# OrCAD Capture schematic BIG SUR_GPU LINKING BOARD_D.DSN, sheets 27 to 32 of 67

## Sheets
27 P27  PCIe Clock Generator-1: size C
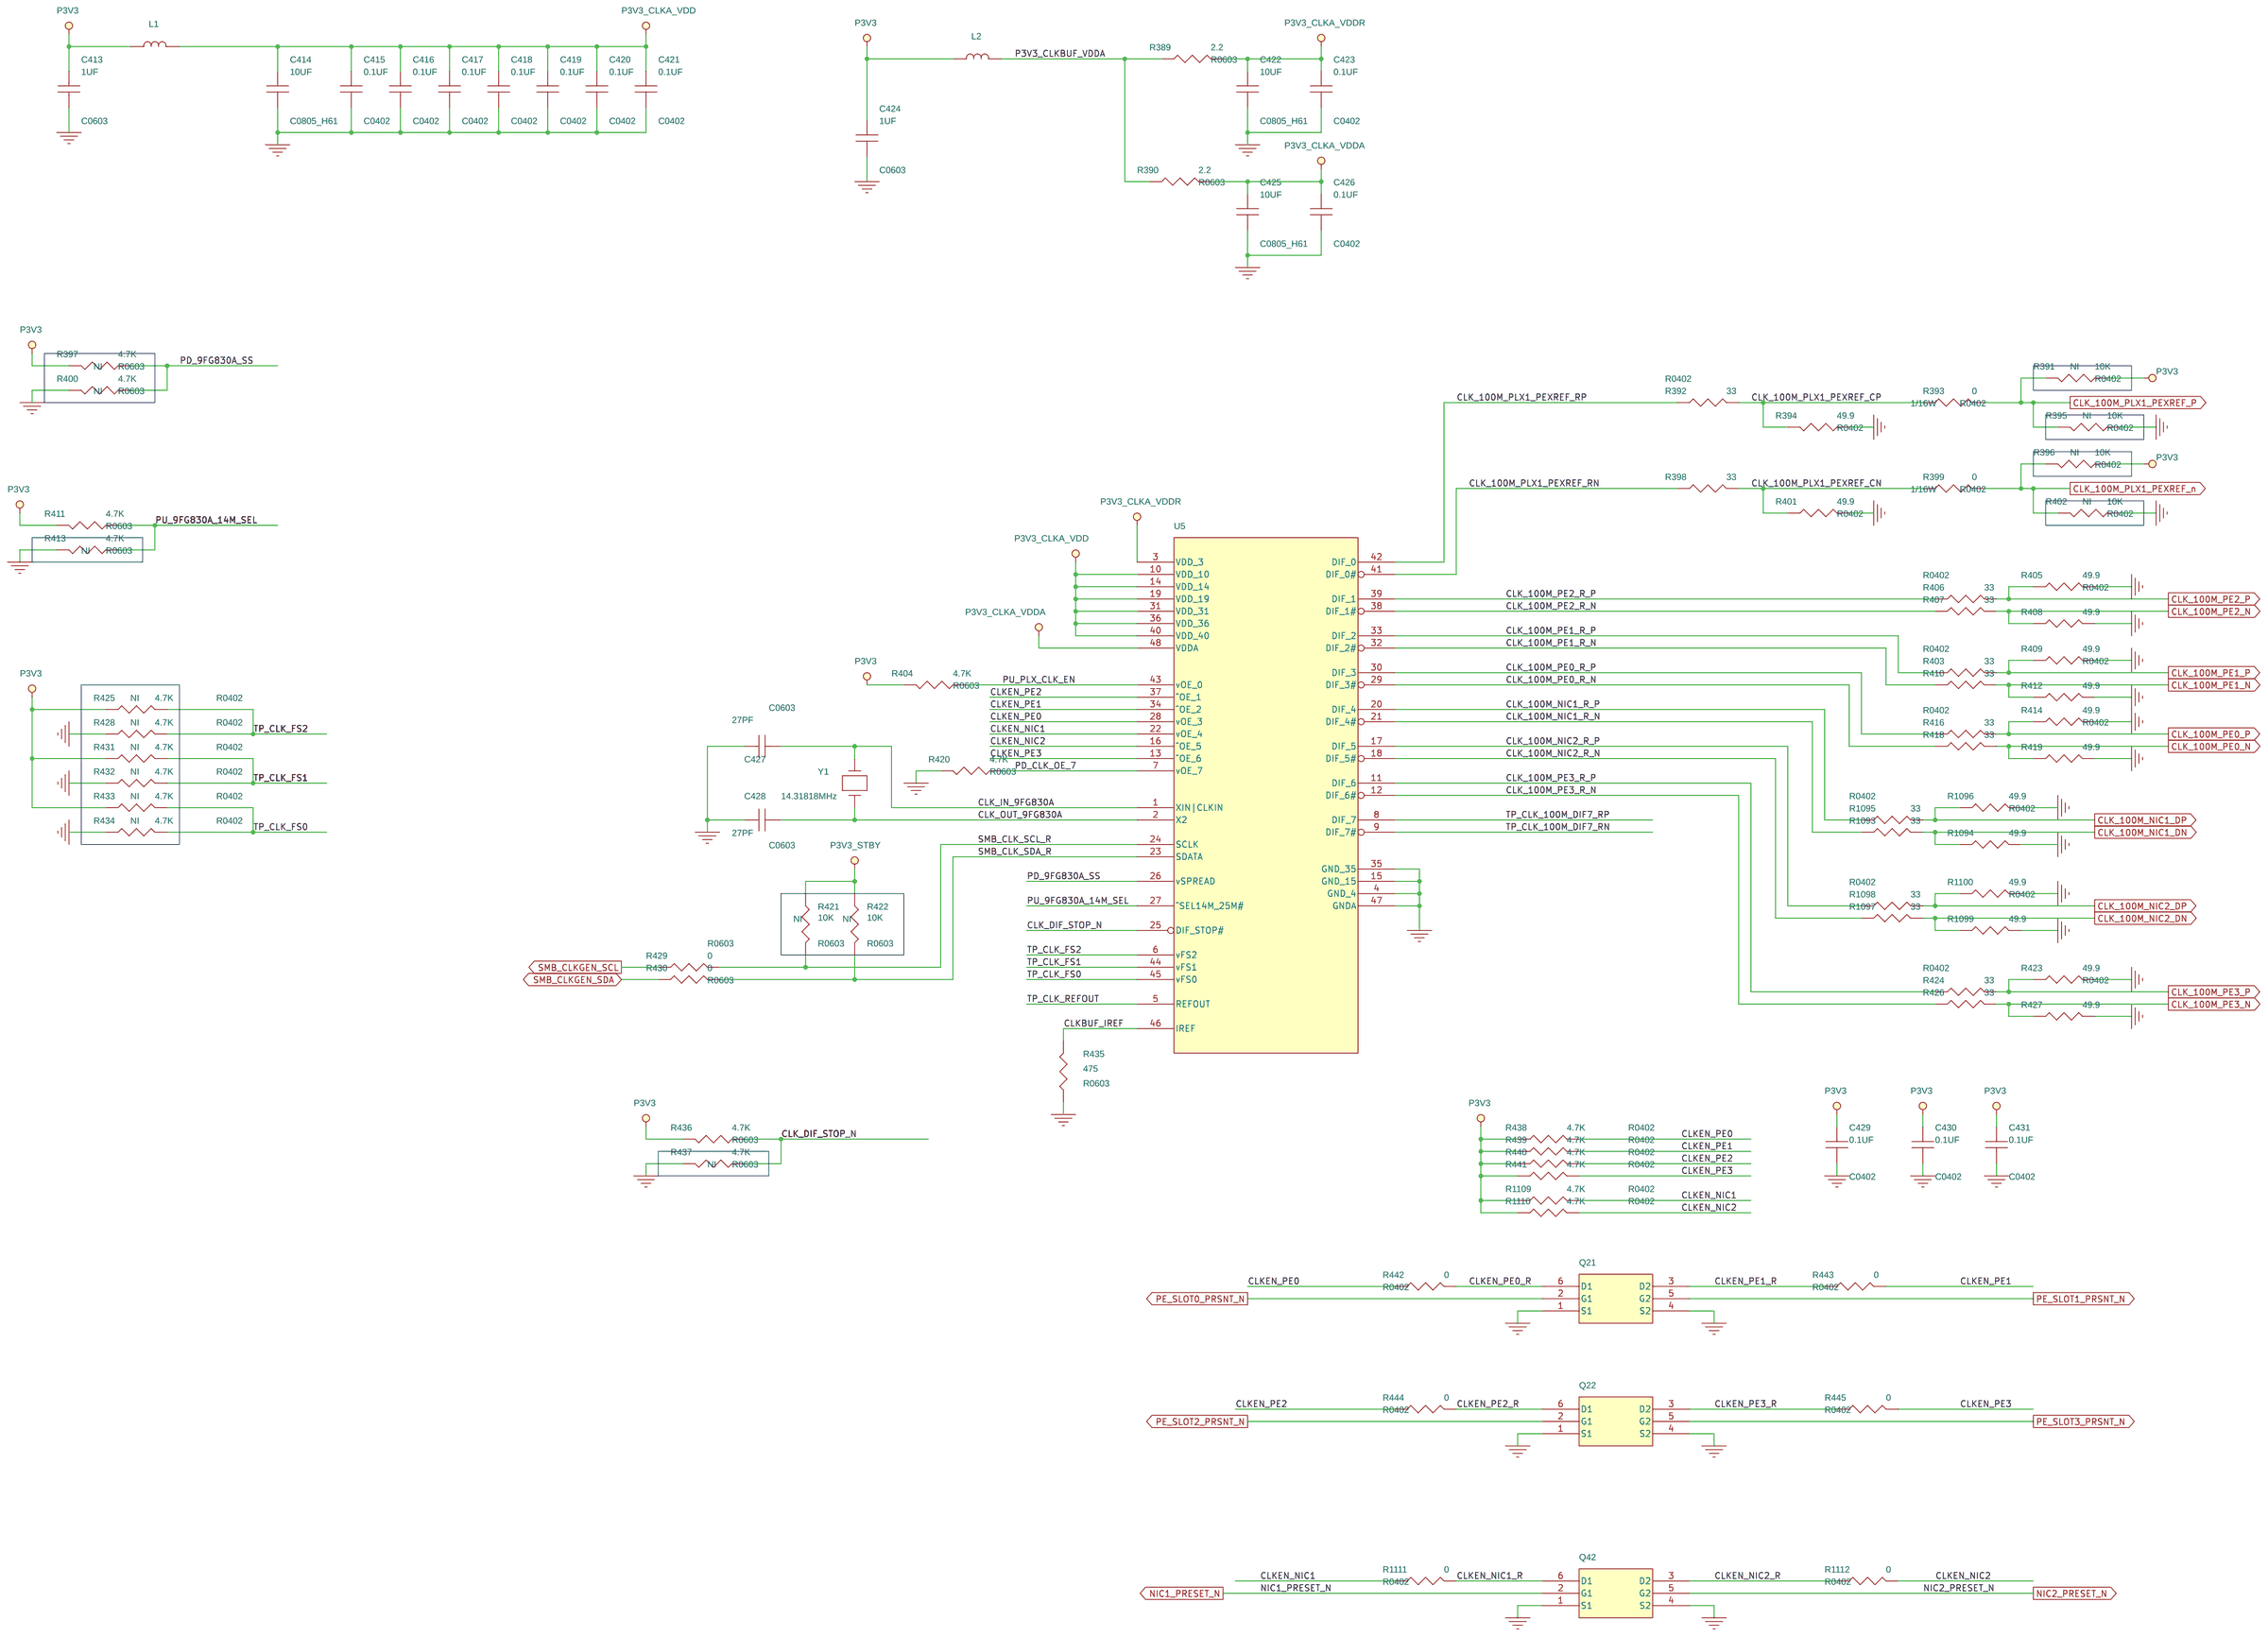
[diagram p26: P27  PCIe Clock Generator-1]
28 P28  PCIe Clock Generator-2: size C
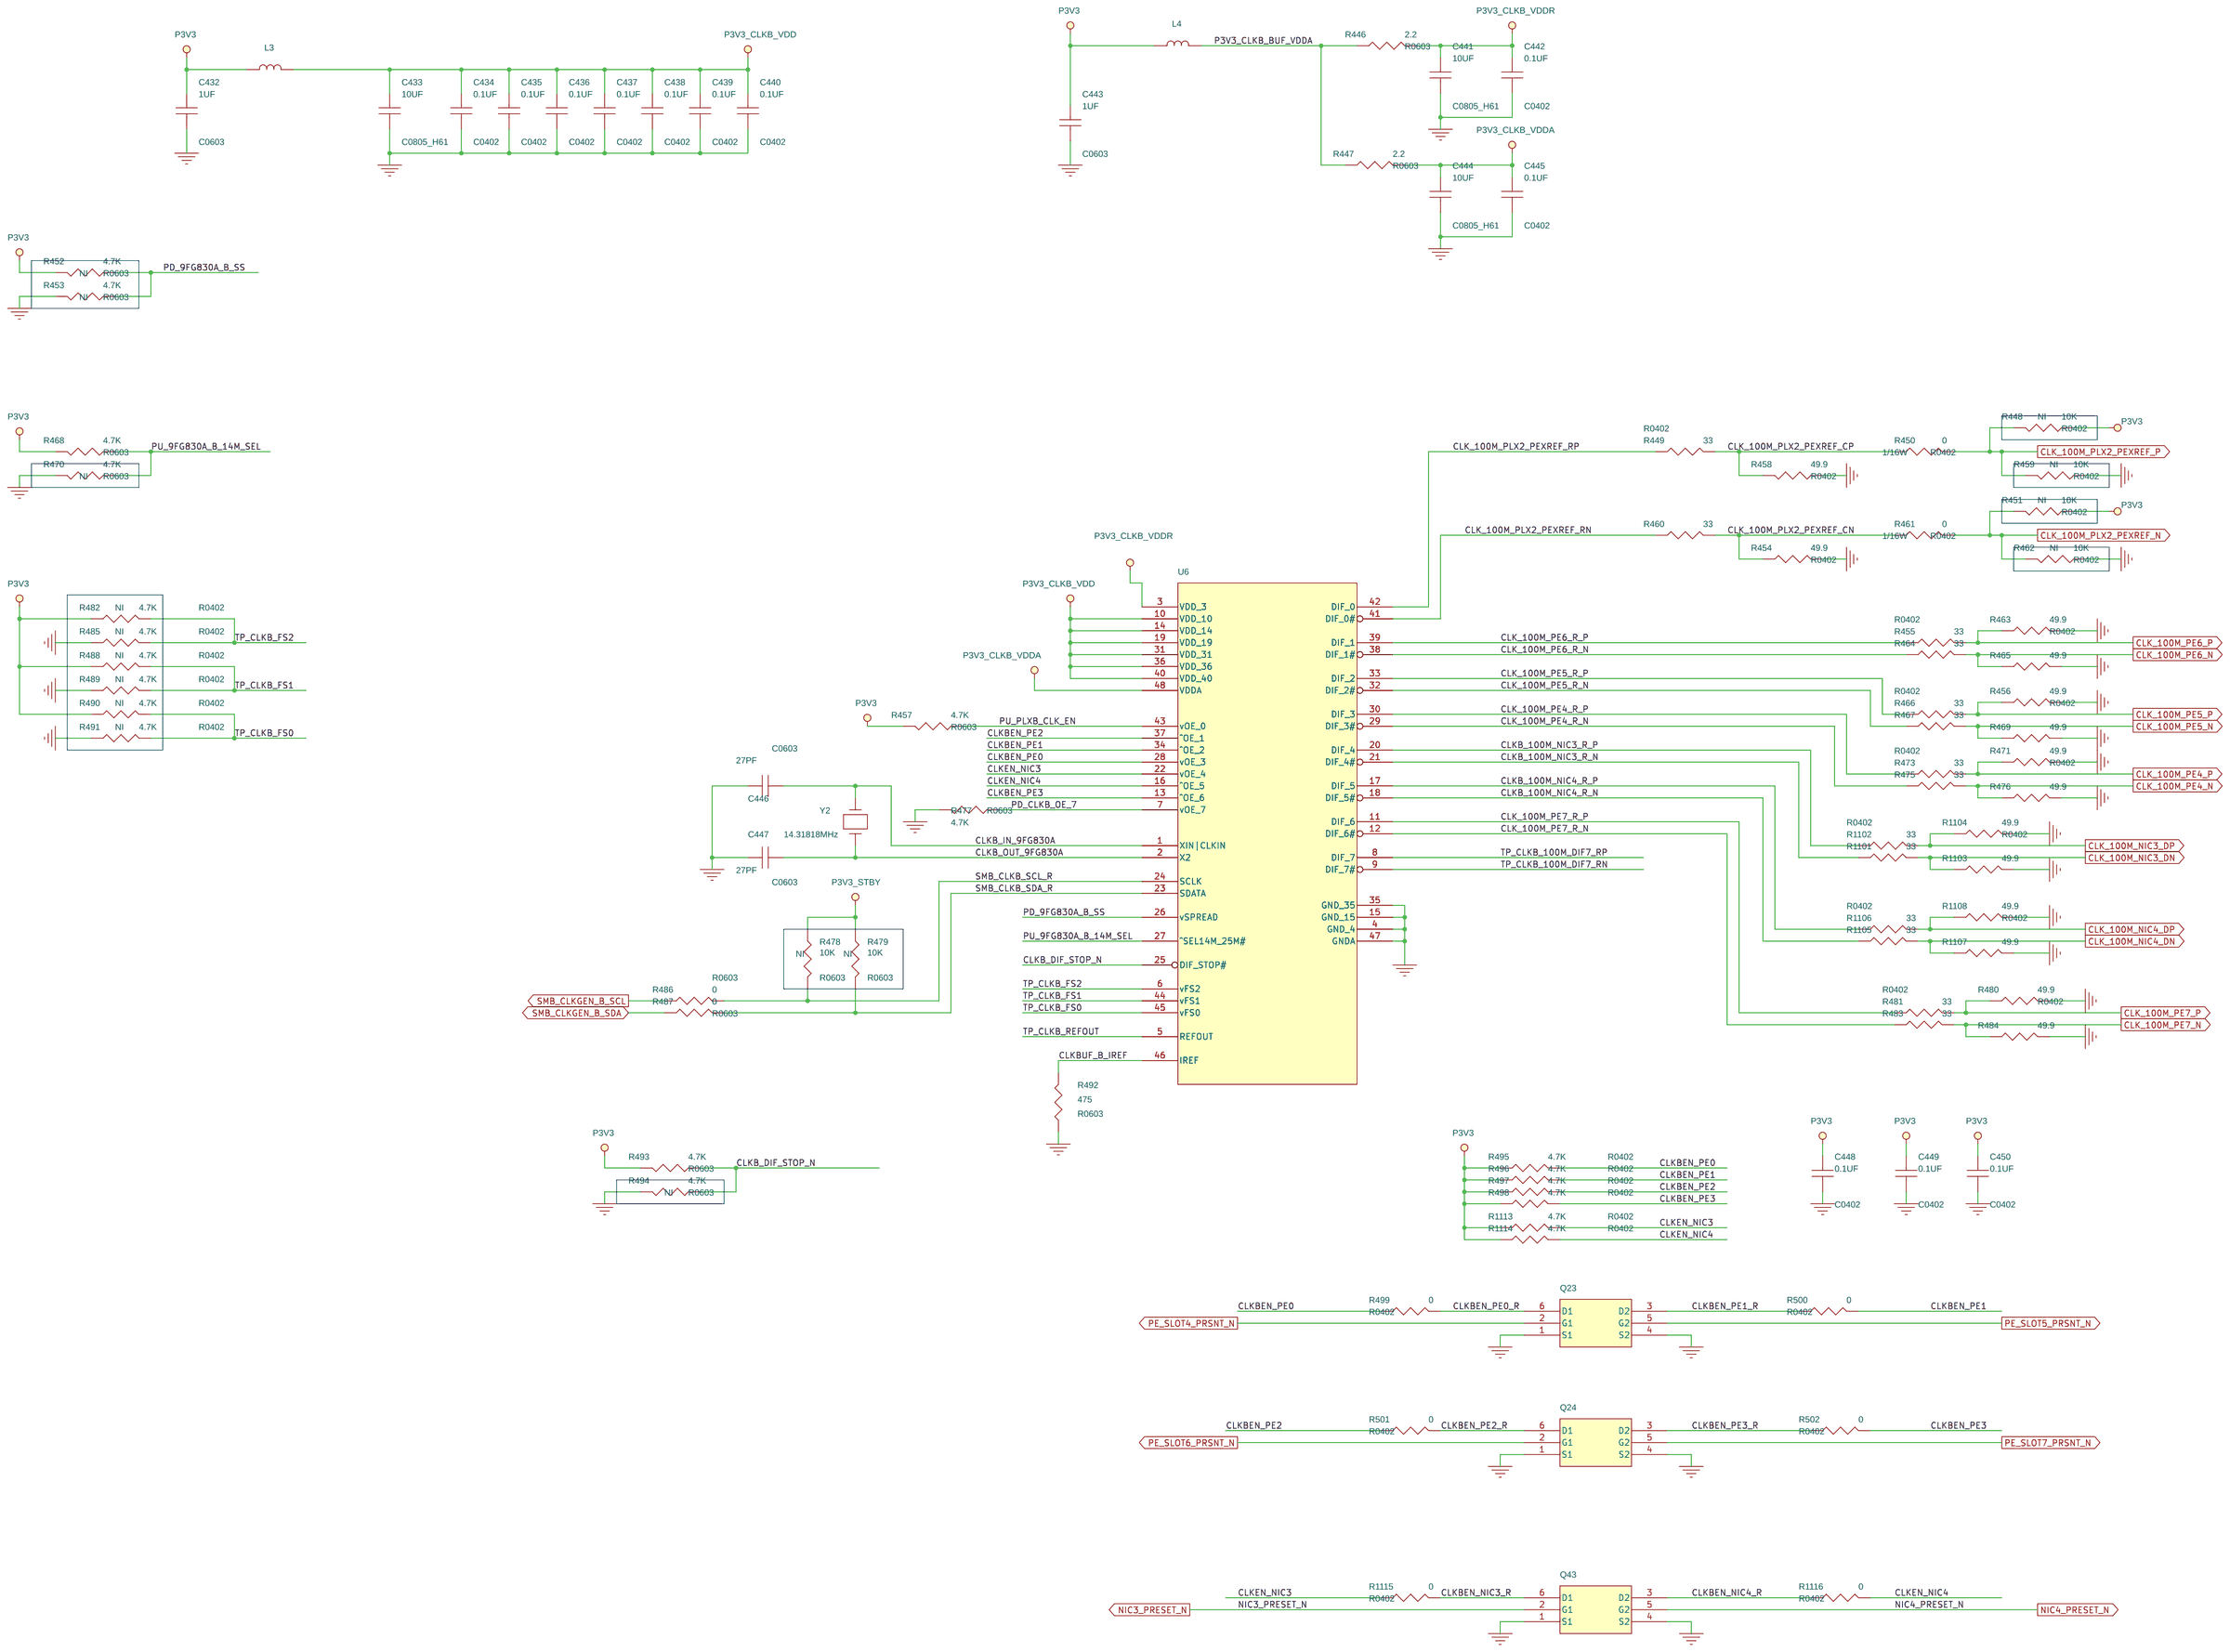
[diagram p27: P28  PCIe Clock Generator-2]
29 P29  MINI SAS HD Conn- A&B: size C
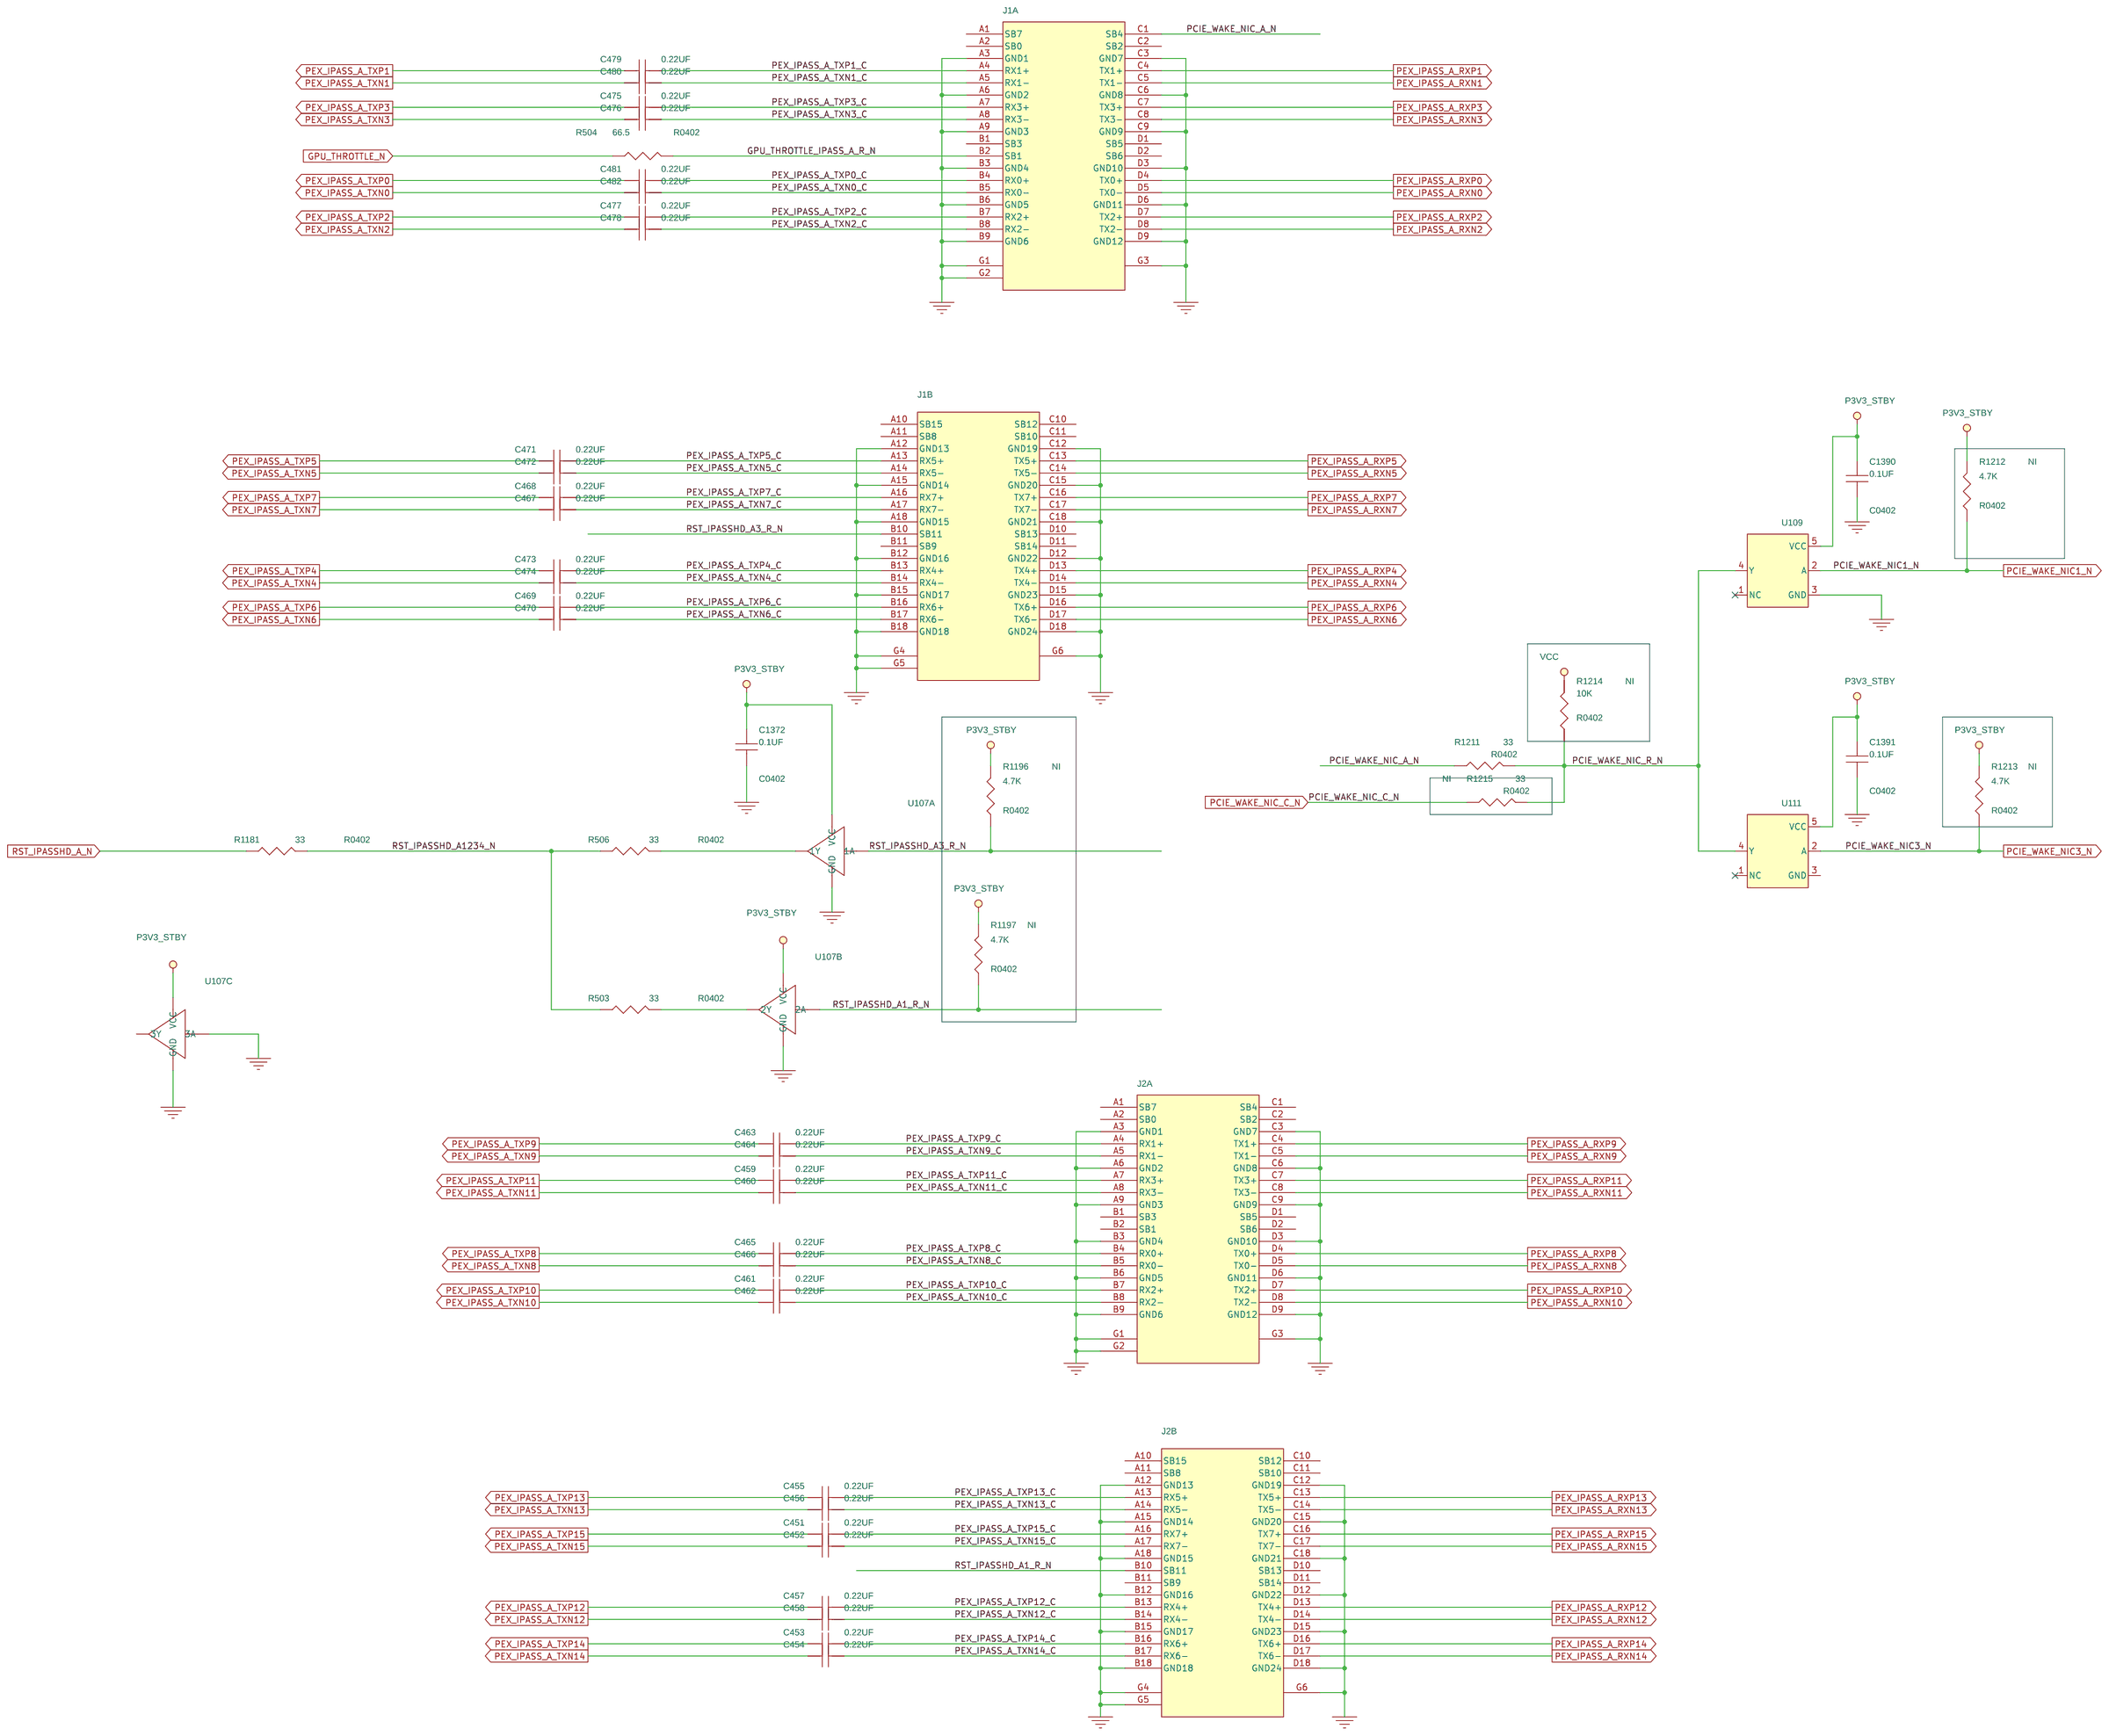
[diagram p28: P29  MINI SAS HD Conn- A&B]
30 P30  MINI SAS HD Conn-C&D: size C
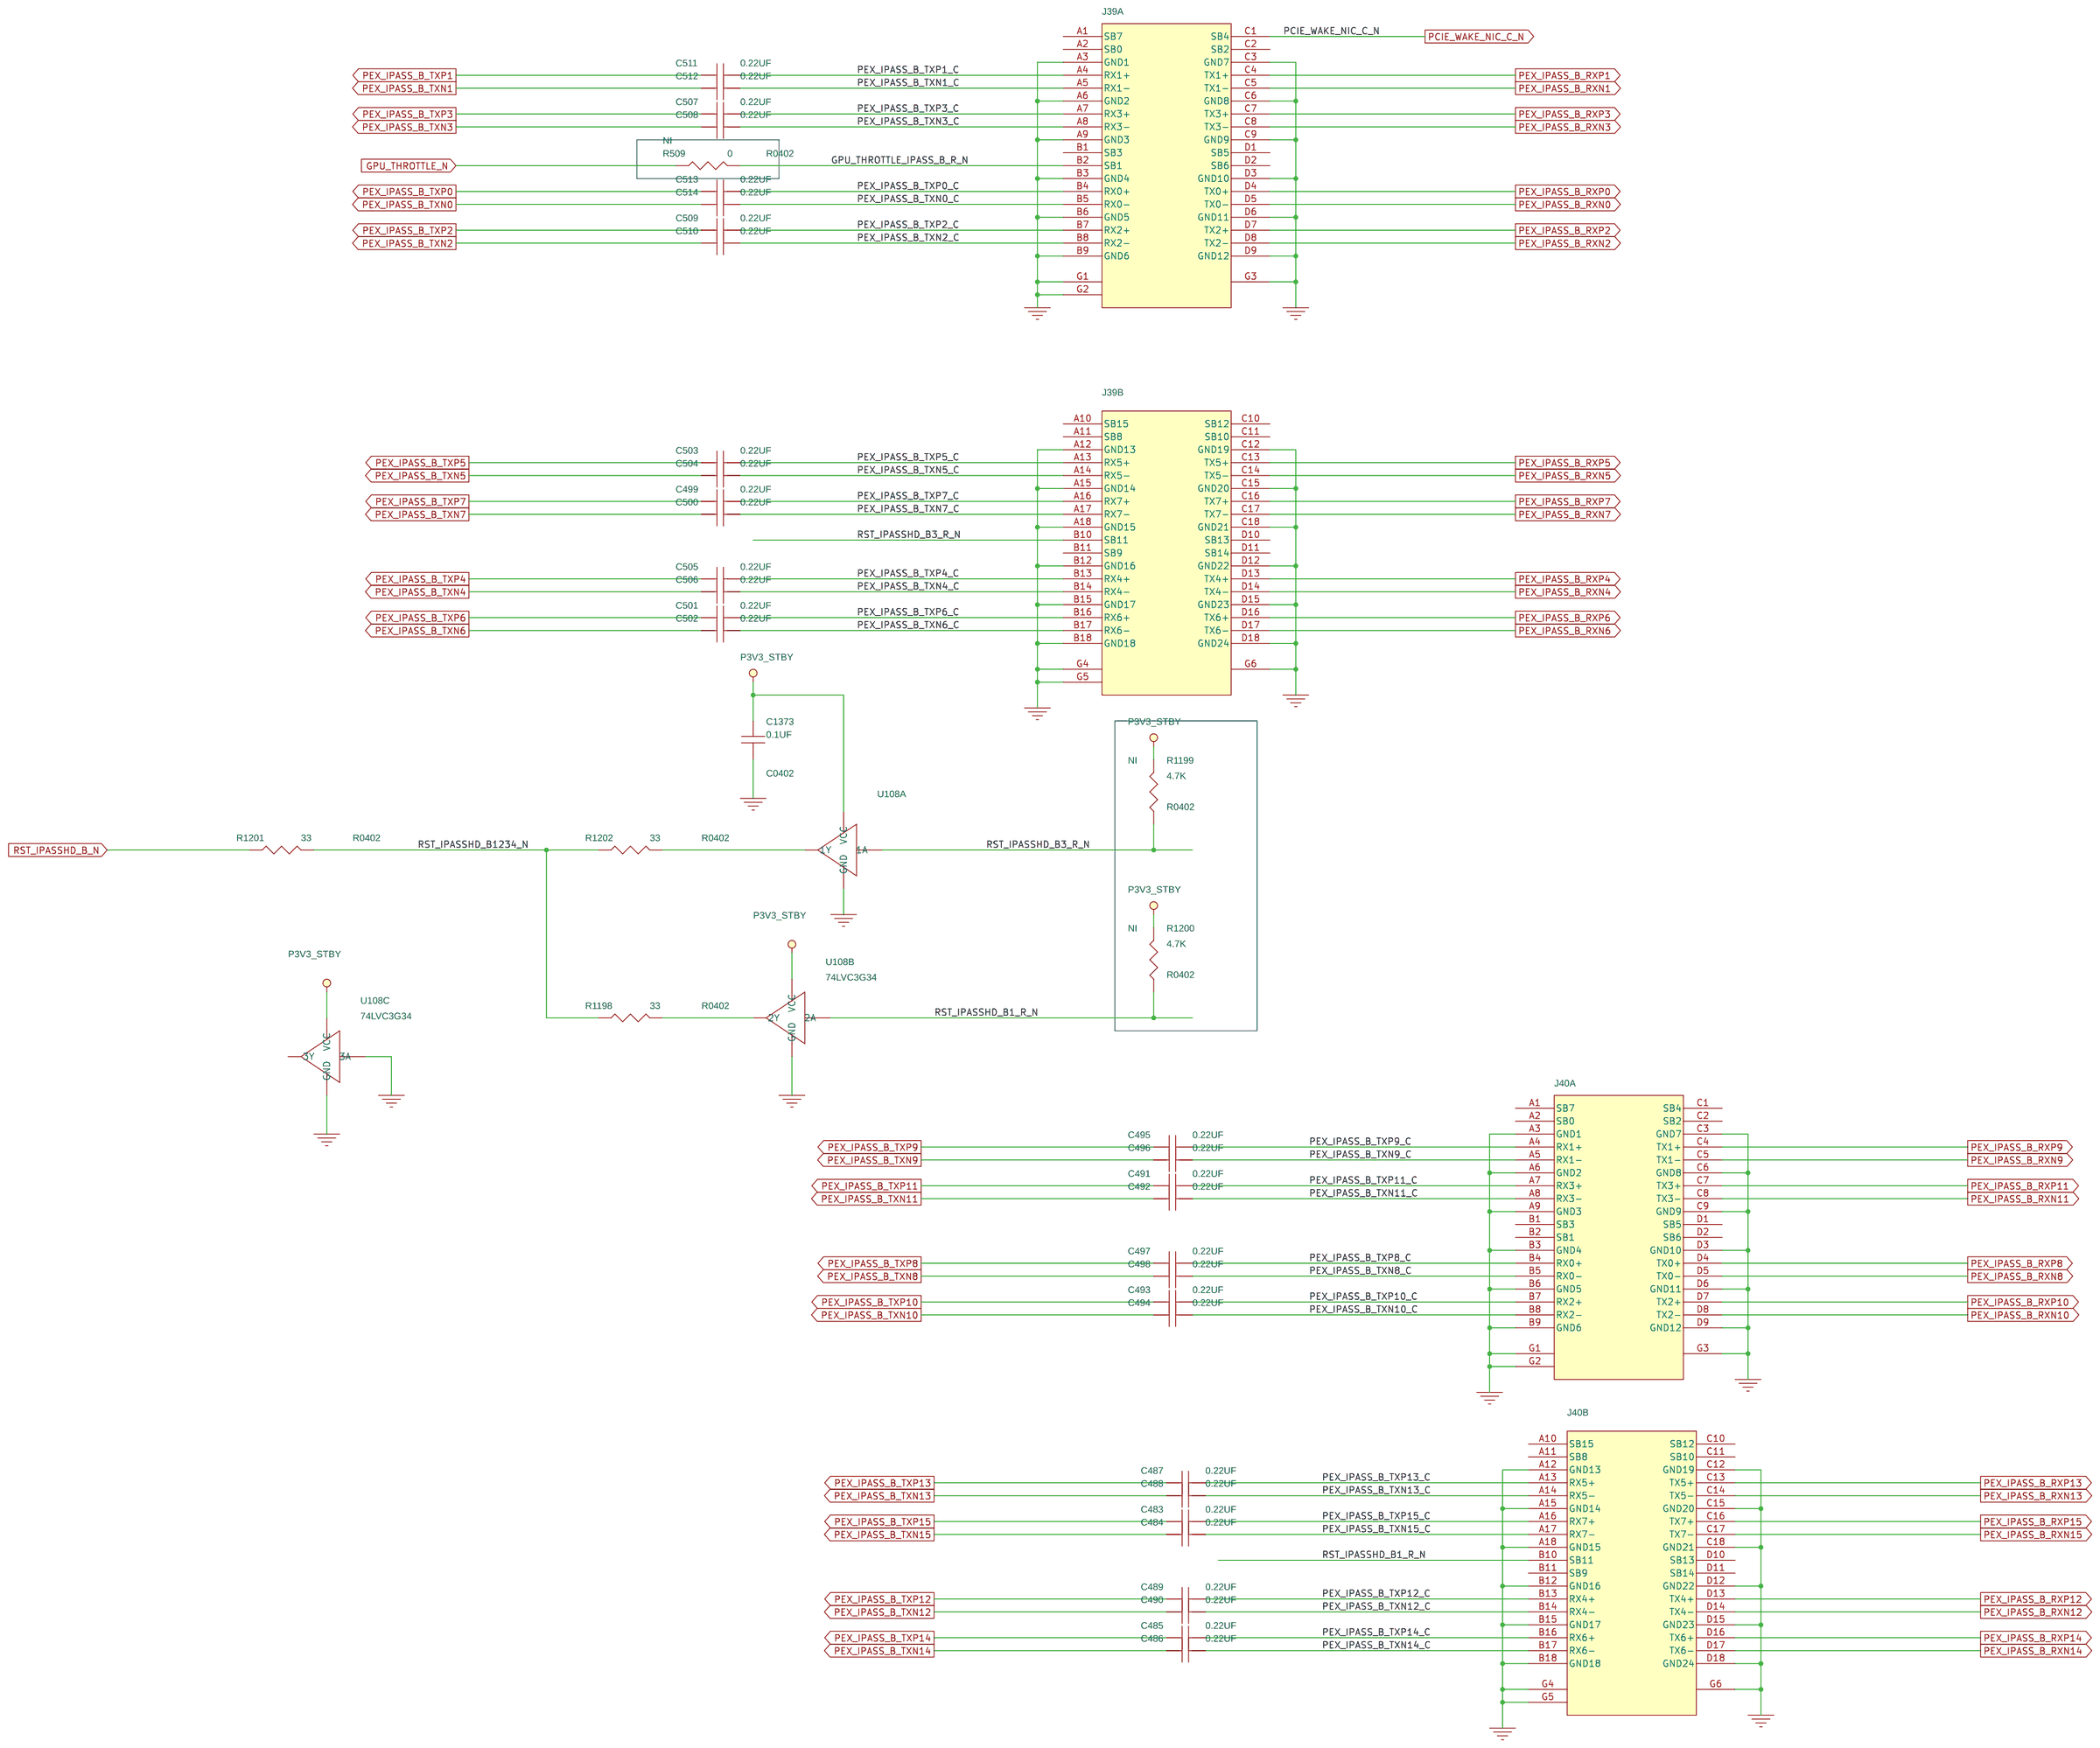
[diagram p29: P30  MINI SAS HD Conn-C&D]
31 P31  PCIe x16 Slot-0: size C
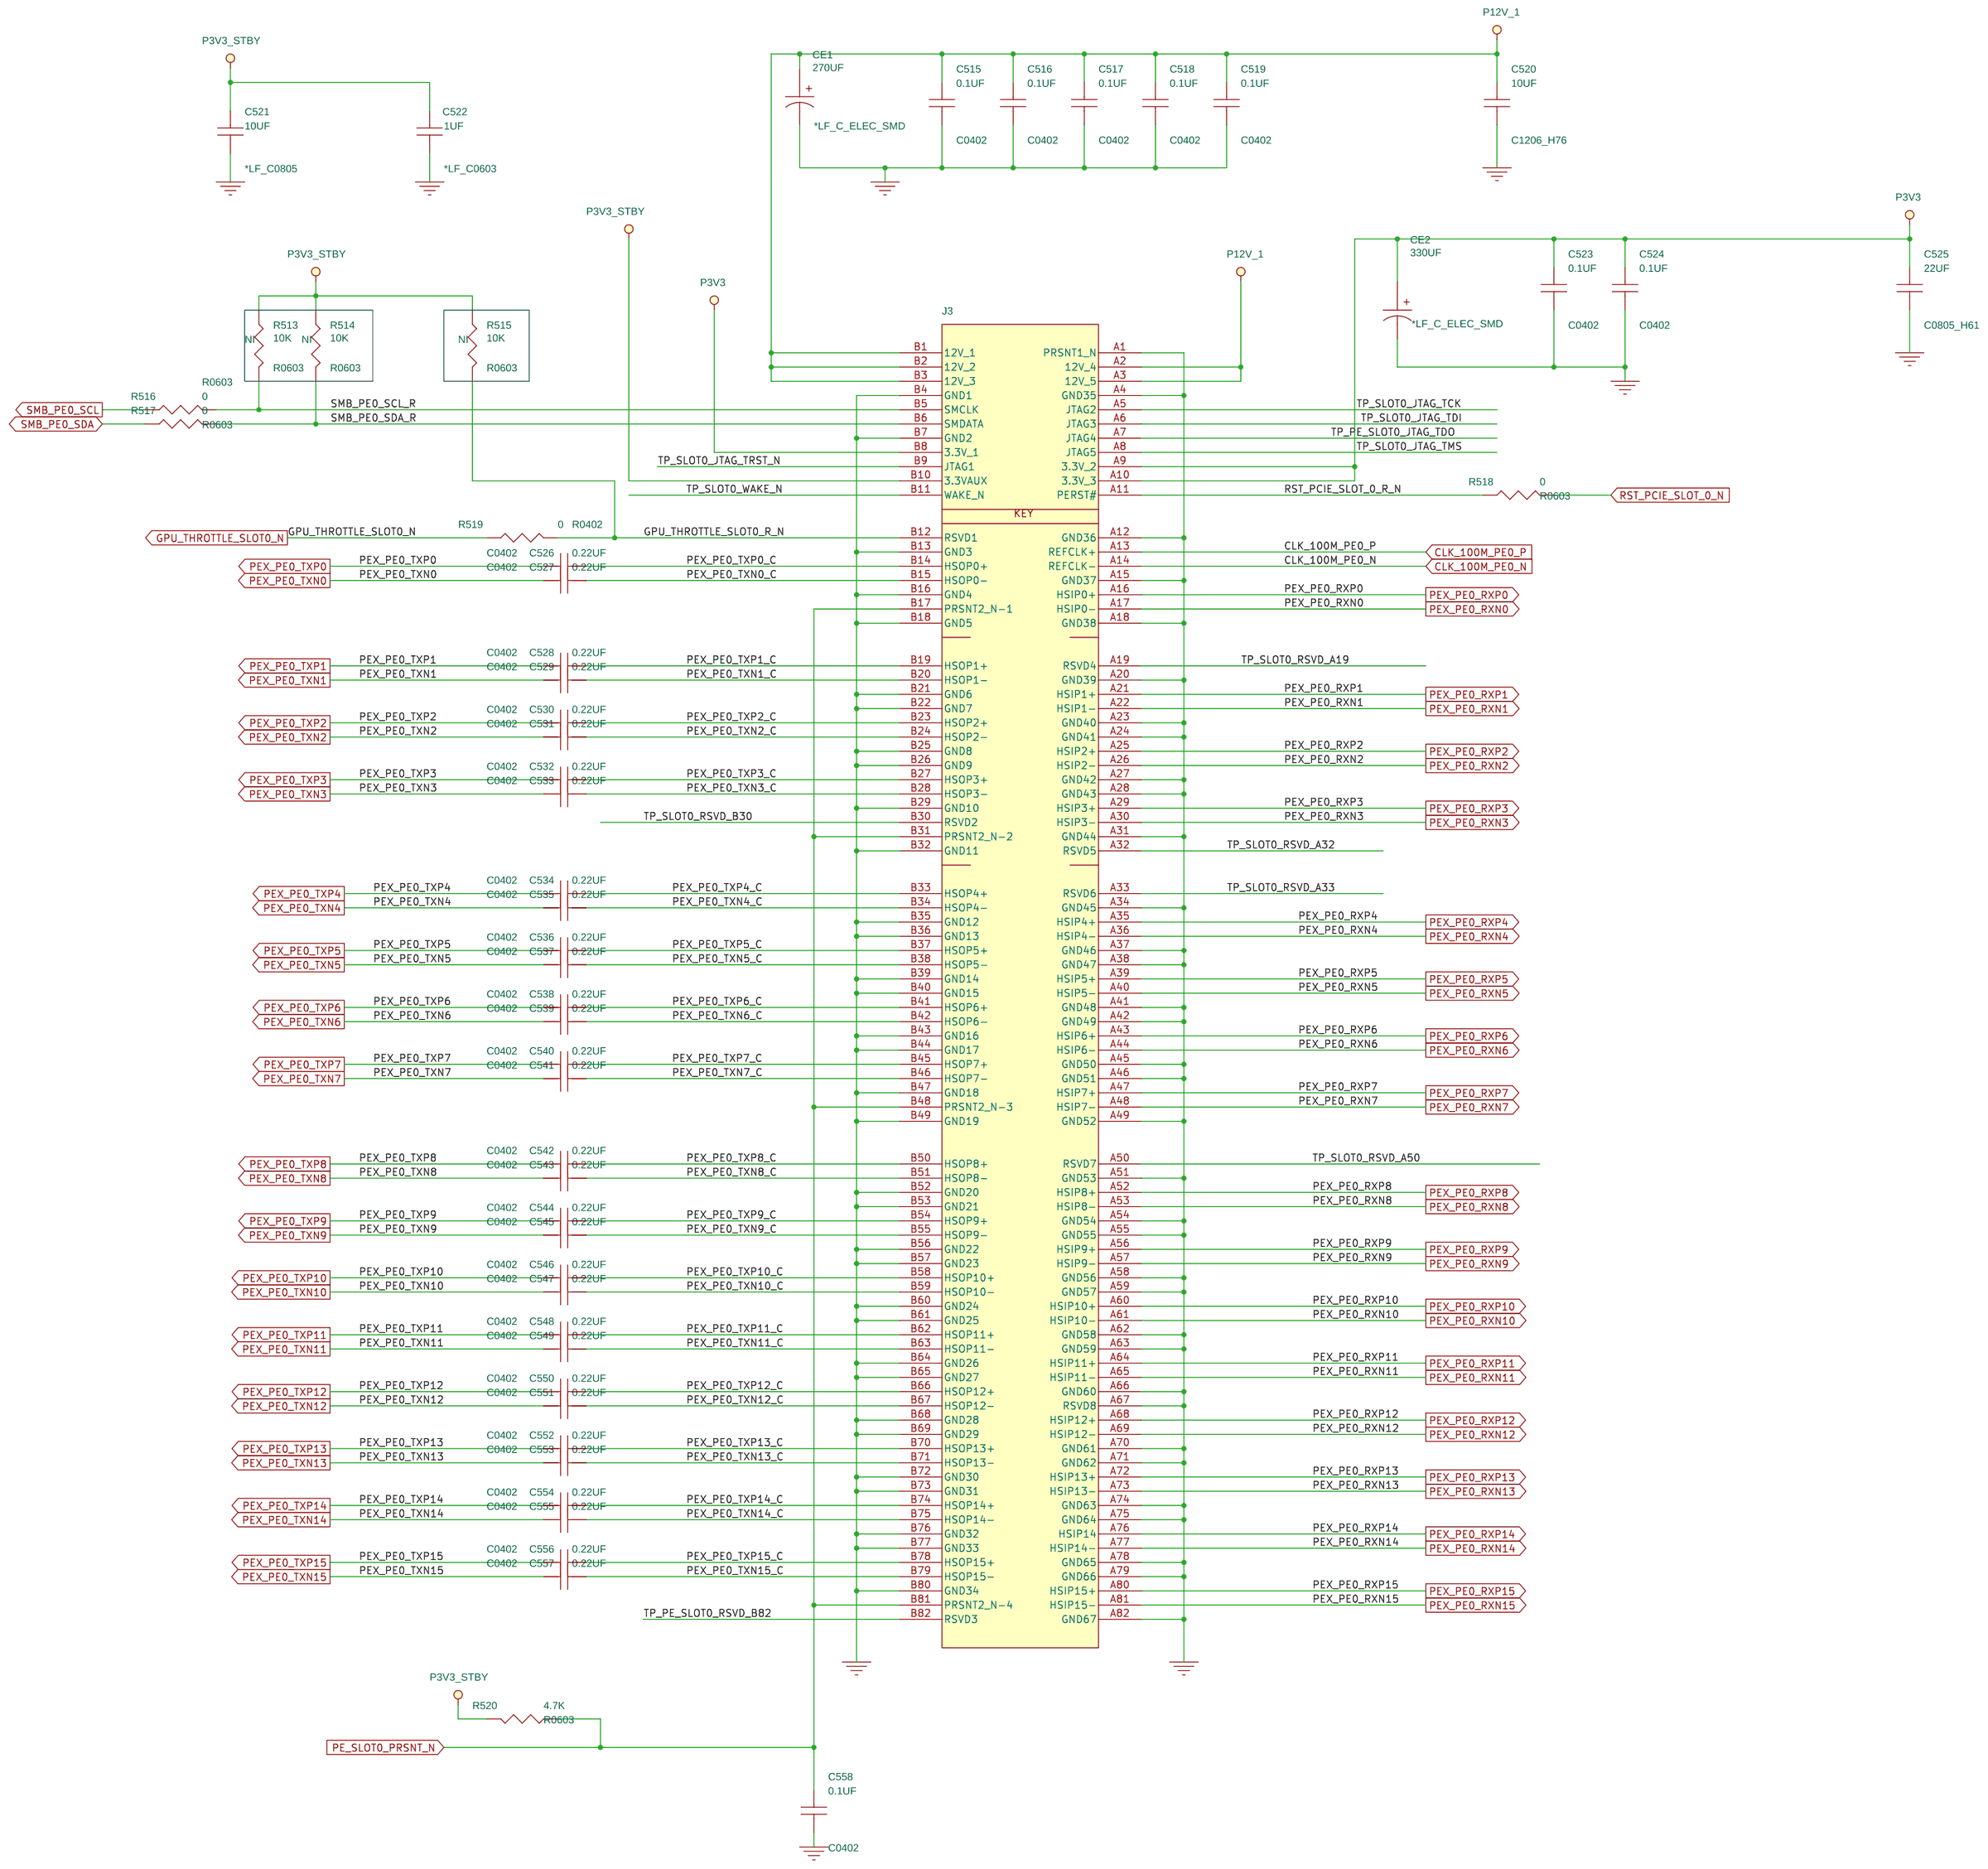
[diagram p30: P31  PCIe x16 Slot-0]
32 P32  PCIe x16 Slot-1: size C
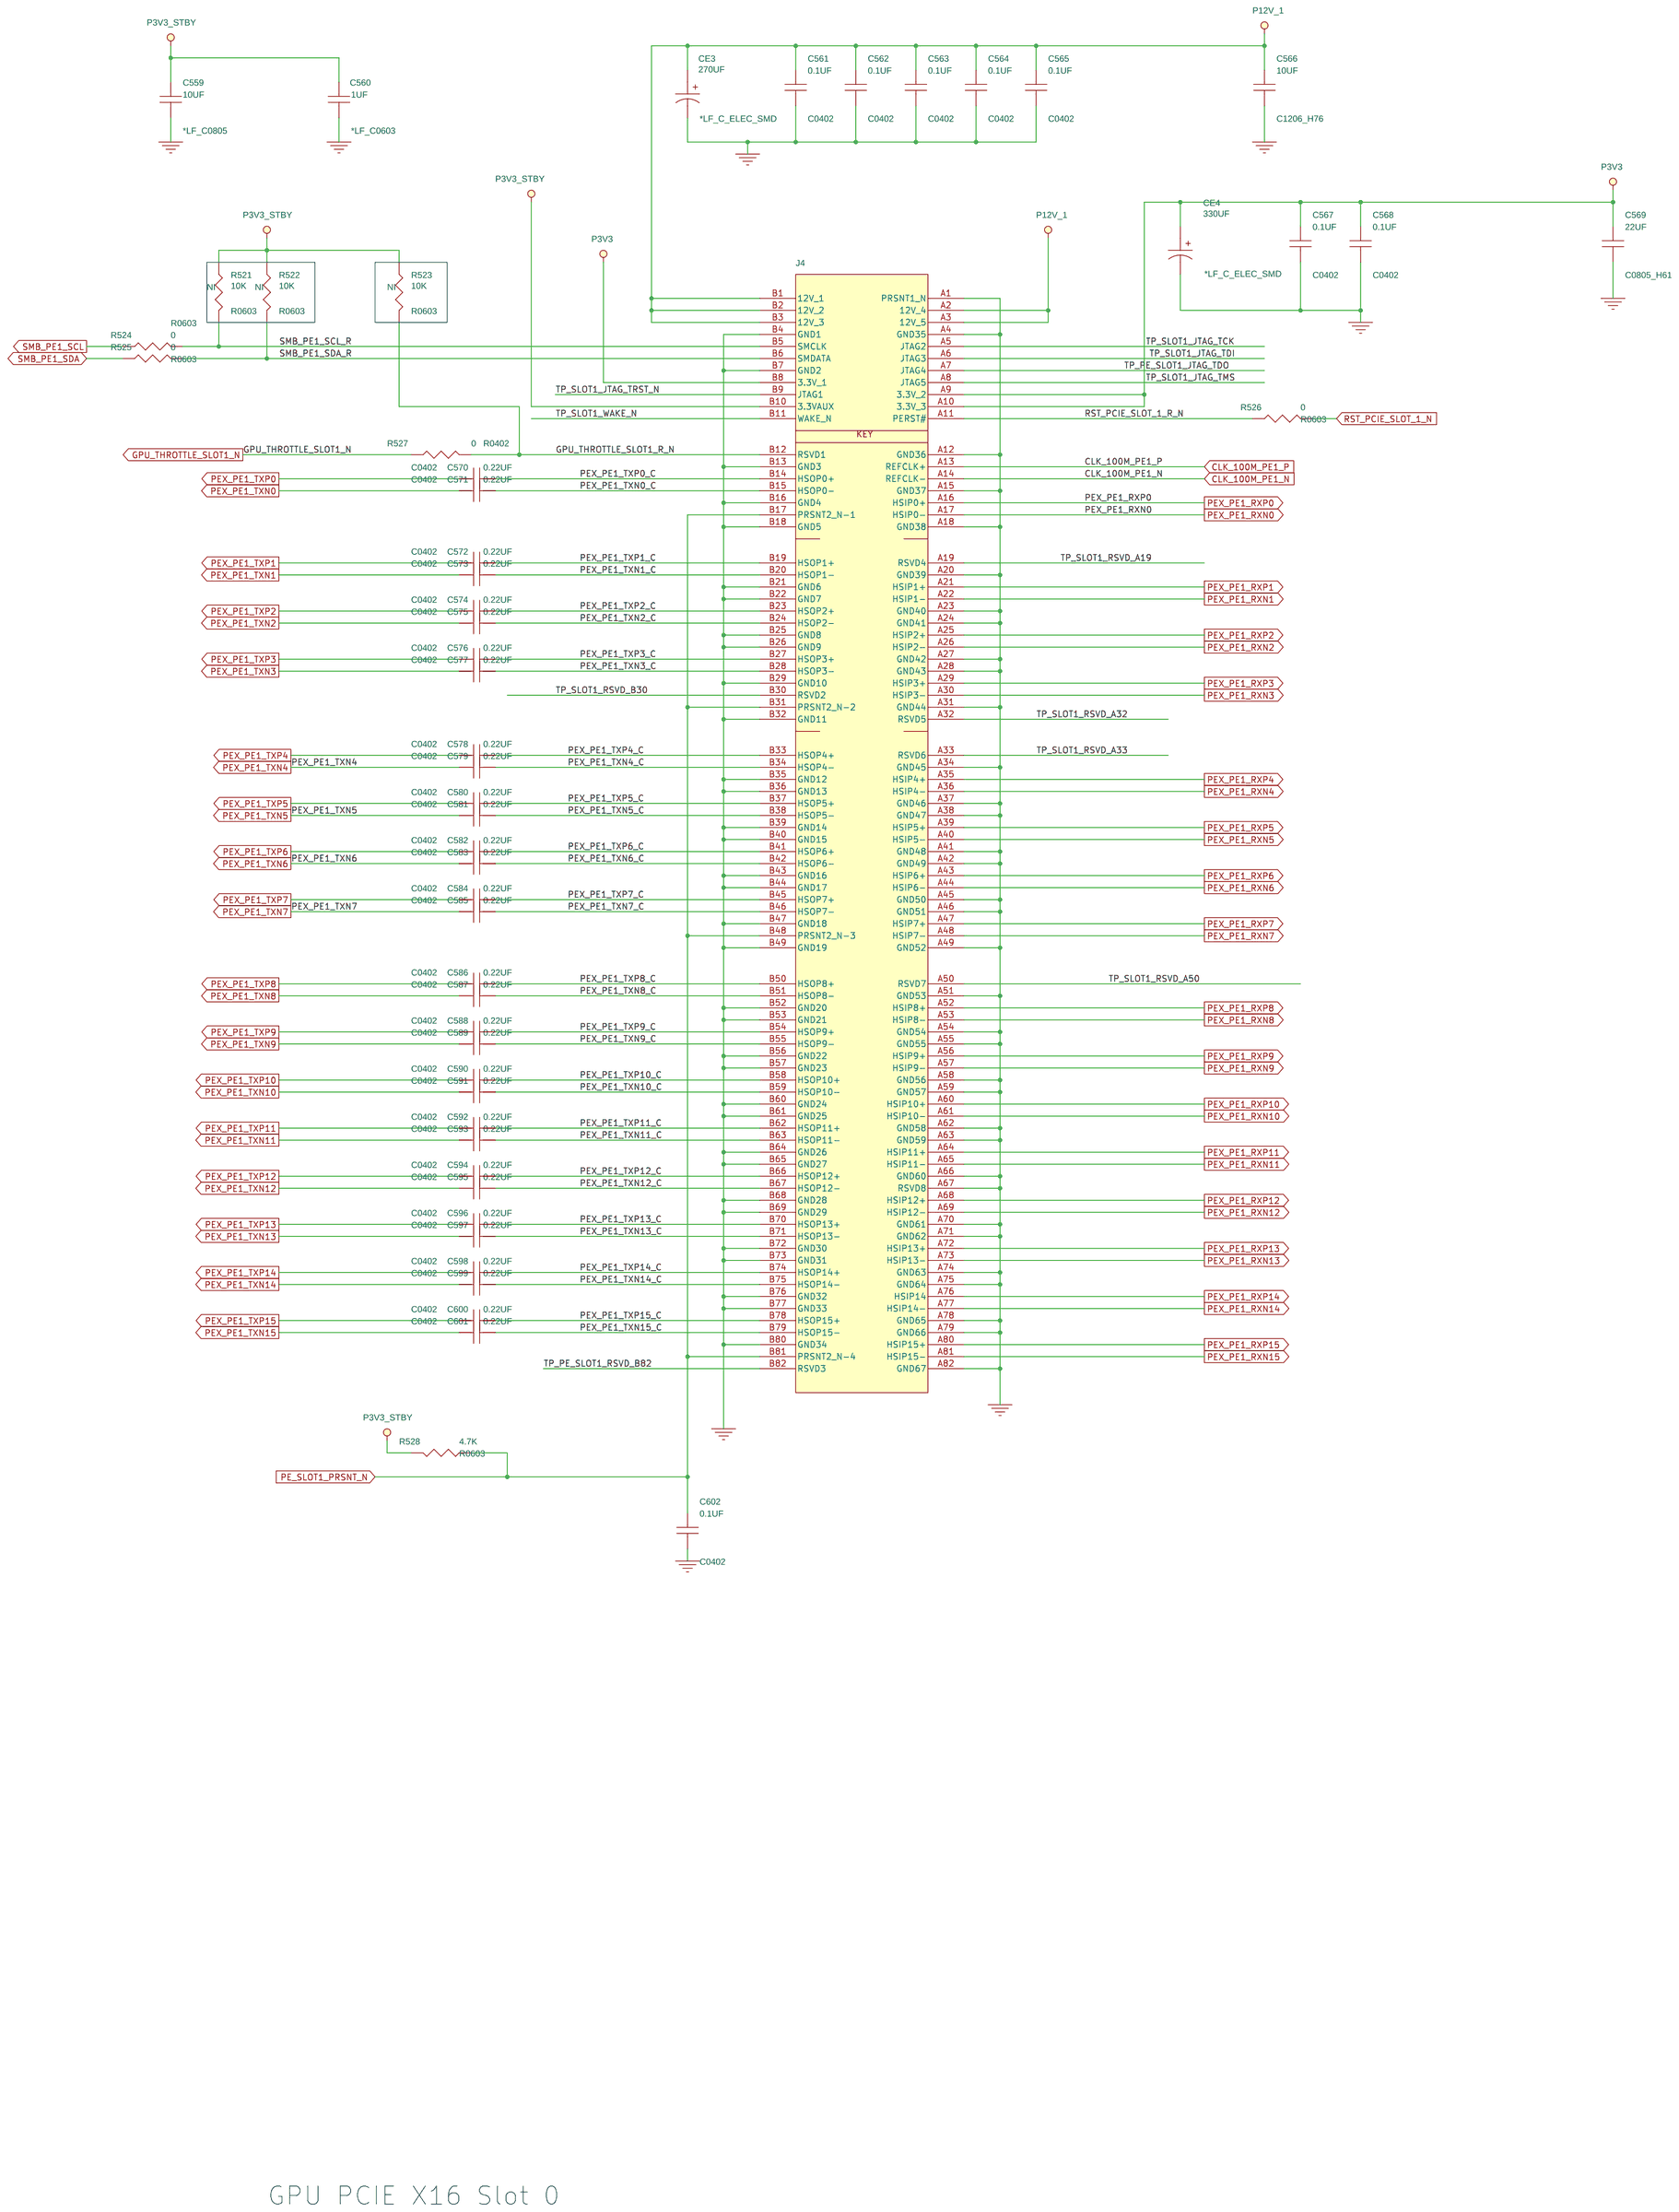
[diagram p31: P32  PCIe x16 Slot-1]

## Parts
sheet P27  PCIe Clock Generator-1
C413  1UF  [C0603]
C414  10UF  [C0805_H61]
C415  0.1UF  [C0402]
C416  0.1UF  [C0402]
C417  0.1UF  [C0402]
C418  0.1UF  [C0402]
C419  0.1UF  [C0402]
C420  0.1UF  [C0402]
C421  0.1UF  [C0402]
C422  10UF  [C0805_H61]
C423  0.1UF  [C0402]
C424  1UF  [C0603]
C425  10UF  [C0805_H61]
C426  0.1UF  [C0402]
C427  27PF  [C0603]
C428  27PF  [C0603]
C429  0.1UF  [C0402]
C430  0.1UF  [C0402]
C431  0.1UF  [C0402]
L1  Inductor  [L0805]
L2  inductor  [L0805]
Q21  DMN601DWK-7  [SOT363A]
Q22  DMN601DWK-7  [SOT363A]
Q42  DMN601DWK-7  [SOT363A]
R389  2.2  [R0603]
R390  2.2  [R0603]
R391  10K  [R0402]
R392  33  [R0402]
R393  0  [R0402]
R394  49.9  [R0402]
R395  10K  [R0402]
R396  10K  [R0402]
R397  4.7K  [R0603]
R398  33  [R0402]
R399  0  [R0402]
R400  4.7K  [R0603]
R401  49.9  [R0402]
R402  10K  [R0402]
R403  33  [R0402]
R404  4.7K  [R0603]
R405  49.9  [R0402]
R406  33  [R0402]
R407  33  [R0402]
R408  49.9  [R0402]
R409  49.9  [R0402]
R410  33  [R0402]
R411  4.7K  [R0603]
R412  49.9  [R0402]
R413  4.7K  [R0603]
R414  49.9  [R0402]
R416  33  [R0402]
R418  33  [R0402]
R419  49.9  [R0402]
R420  4.7K  [R0603]
R421  10K  [R0603]
R422  10K  [R0603]
R423  49.9  [R0402]
R424  33  [R0402]
R425  4.7K  [R0402]
R426  33  [R0402]
R427  49.9  [R0402]
R428  4.7K  [R0402]
R429  0  [R0603]
R430  0  [R0603]
R431  4.7K  [R0402]
R432  4.7K  [R0402]
R433  4.7K  [R0402]
R434  4.7K  [R0402]
R435  475  [R0603]
R436  4.7K  [R0603]
R437  4.7K  [R0603]
R438  4.7K  [R0402]
R439  4.7K  [R0402]
R440  4.7K  [R0402]
R441  4.7K  [R0402]
R442  0  [R0402]
R443  0  [R0402]
R444  0  [R0402]
R445  0  [R0402]
R1093  33  [R0402]
R1094  49.9  [R0402]
R1095  33  [R0402]
R1096  49.9  [R0402]
R1097  33  [R0402]
R1098  33  [R0402]
R1099  49.9  [R0402]
R1100  49.9  [R0402]
R1109  4.7K  [R0402]
R1110  4.7K  [R0402]
R1111  0  [R0402]
R1112  0  [R0402]
U5  IC  [SSOP48]
Y1  14.31818MHz  [X_HC49A]
sheet P28  PCIe Clock Generator-2
C432  1UF  [C0603]
C433  10UF  [C0805_H61]
C434  0.1UF  [C0402]
C435  0.1UF  [C0402]
C436  0.1UF  [C0402]
C437  0.1UF  [C0402]
C438  0.1UF  [C0402]
C439  0.1UF  [C0402]
C440  0.1UF  [C0402]
C441  10UF  [C0805_H61]
C442  0.1UF  [C0402]
C443  1UF  [C0603]
C444  10UF  [C0805_H61]
C445  0.1UF  [C0402]
C446  27PF  [C0603]
C447  27PF  [C0603]
C448  0.1UF  [C0402]
C449  0.1UF  [C0402]
C450  0.1UF  [C0402]
L3  inductor  [L0805]
L4  inductor  [L0805]
Q23  DMN601DWK-7  [SOT363A]
Q24  DMN601DWK-7  [SOT363A]
Q43  DMN601DWK-7  [SOT363A]
R446  2.2  [R0603]
R447  2.2  [R0603]
R448  10K  [R0402]
R449  33  [R0402]
R450  0  [R0402]
R451  10K  [R0402]
R452  4.7K  [R0603]
R453  4.7K  [R0603]
R454  49.9  [R0402]
R455  33  [R0402]
R456  49.9  [R0402]
R457  4.7K  [R0603]
R458  49.9  [R0402]
R459  10K  [R0402]
R460  33  [R0402]
R461  0  [R0402]
R462  10K  [R0402]
R463  49.9  [R0402]
R464  33  [R0402]
R465  49.9  [R0402]
R466  33  [R0402]
R467  33  [R0402]
R468  4.7K  [R0603]
R469  49.9  [R0402]
R470  4.7K  [R0603]
R471  49.9  [R0402]
R473  33  [R0402]
R475  33  [R0402]
R476  49.9  [R0402]
R477  4.7K  [R0603]
R478  10K  [R0603]
R479  10K  [R0603]
R480  49.9  [R0402]
R481  33  [R0402]
R482  4.7K  [R0402]
R483  33  [R0402]
R484  49.9  [R0402]
R485  4.7K  [R0402]
R486  0  [R0603]
R487  0  [R0603]
R488  4.7K  [R0402]
R489  4.7K  [R0402]
R490  4.7K  [R0402]
R491  4.7K  [R0402]
R492  475  [R0603]
R493  4.7K  [R0603]
R494  4.7K  [R0603]
R495  4.7K  [R0402]
R496  4.7K  [R0402]
R497  4.7K  [R0402]
R498  4.7K  [R0402]
R499  0  [R0402]
R500  0  [R0402]
R501  0  [R0402]
R502  0  [R0402]
R1101  33  [R0402]
R1102  33  [R0402]
R1103  49.9  [R0402]
R1104  49.9  [R0402]
R1105  33  [R0402]
R1106  33  [R0402]
R1107  49.9  [R0402]
R1108  49.9  [R0402]
R1113  4.7K  [R0402]
R1114  4.7K  [R0402]
R1115  0  [R0402]
R1116  0  [R0402]
U6  IC  [SSOP48]
Y2  14.31818MHz  [X_HC49A]
sheet P29  MINI SAS HD Conn- A&B
C451  0.22UF  [C0402]
C452  0.22UF  [C0402]
C453  0.22UF  [C0402]
C454  0.22UF  [C0402]
C455  0.22UF  [C0402]
C456  0.22UF  [C0402]
C457  0.22UF  [C0402]
C458  0.22UF  [C0402]
C459  0.22UF  [C0402]
C460  0.22UF  [C0402]
C461  0.22UF  [C0402]
C462  0.22UF  [C0402]
C463  0.22UF  [C0402]
C464  0.22UF  [C0402]
C465  0.22UF  [C0402]
C466  0.22UF  [C0402]
C467  0.22UF  [C0402]
C468  0.22UF  [C0402]
C469  0.22UF  [C0402]
C470  0.22UF  [C0402]
C471  0.22UF  [C0402]
C472  0.22UF  [C0402]
C473  0.22UF  [C0402]
C474  0.22UF  [C0402]
C475  0.22UF  [C0402]
C476  0.22UF  [C0402]
C477  0.22UF  [C0402]
C478  0.22UF  [C0402]
C479  0.22UF  [C0402]
C480  0.22UF  [C0402]
C481  0.22UF  [C0402]
C482  0.22UF  [C0402]
C1372  0.1UF  [C0402]
C1390  0.1UF  [C0402]
C1391  0.1UF  [C0402]
J1  SCONN72  [CON_F72S4H8D_P0-75W3-53_LDH]  (sections A,B)
J2  SCONN72  [CON_F72S4H8D_P0-75W3-53_LDH]  (sections A,B)
R503  33  [R0402]
R504  66.5  [R0402]
R506  33  [R0402]
R1181  33  [R0402]
R1196  4.7K  [R0402]
R1197  4.7K  [R0402]
R1211  33  [R0402]
R1212  4.7K  [R0402]
R1213  4.7K  [R0402]
R1214  10K  [R0402]
R1215  33  [R0402]
U107  74LVC3G34  [SSOP8]  (sections A,B,C)
U109  SN74LVC1G07  [SOT23-5]
U111  SN74LVC1G07  [SOT23-5]
sheet P30  MINI SAS HD Conn-C&D
C483  0.22UF  [C0402]
C484  0.22UF  [C0402]
C485  0.22UF  [C0402]
C486  0.22UF  [C0402]
C487  0.22UF  [C0402]
C488  0.22UF  [C0402]
C489  0.22UF  [C0402]
C490  0.22UF  [C0402]
C491  0.22UF  [C0402]
C492  0.22UF  [C0402]
C493  0.22UF  [C0402]
C494  0.22UF  [C0402]
C495  0.22UF  [C0402]
C496  0.22UF  [C0402]
C497  0.22UF  [C0402]
C498  0.22UF  [C0402]
C499  0.22UF  [C0402]
C500  0.22UF  [C0402]
C501  0.22UF  [C0402]
C502  0.22UF  [C0402]
C503  0.22UF  [C0402]
C504  0.22UF  [C0402]
C505  0.22UF  [C0402]
C506  0.22UF  [C0402]
C507  0.22UF  [C0402]
C508  0.22UF  [C0402]
C509  0.22UF  [C0402]
C510  0.22UF  [C0402]
C511  0.22UF  [C0402]
C512  0.22UF  [C0402]
C513  0.22UF  [C0402]
C514  0.22UF  [C0402]
C1373  0.1UF  [C0402]
J39  SCONN72  [CON_F72S4H8D_P0-75W3-53_LDH]  (sections A,B)
J40  SCONN72  [CON_F72S4H8D_P0-75W3-53_LDH]  (sections A,B)
R509  0  [R0402]
R1198  33  [R0402]
R1199  4.7K  [R0402]
R1200  4.7K  [R0402]
R1201  33  [R0402]
R1202  33  [R0402]
U108  74LVC3G34  [SSOP8]  (sections A,B,C)
sheet P31  PCIe x16 Slot-0
C515  0.1UF  [C0402]
C516  0.1UF  [C0402]
C517  0.1UF  [C0402]
C518  0.1UF  [C0402]
C519  0.1UF  [C0402]
C520  10UF  [C1206_H76]
C521  10UF  [C0805_H61]
C522  1UF  [C0603]
C523  0.1UF  [C0402]
C524  0.1UF  [C0402]
C525  22UF  [C0805_H61]
C526  0.22UF  [C0402]
C527  0.22UF  [C0402]
C528  0.22UF  [C0402]
C529  0.22UF  [C0402]
C530  0.22UF  [C0402]
C531  0.22UF  [C0402]
C532  0.22UF  [C0402]
C533  0.22UF  [C0402]
C534  0.22UF  [C0402]
C535  0.22UF  [C0402]
C536  0.22UF  [C0402]
C537  0.22UF  [C0402]
C538  0.22UF  [C0402]
C539  0.22UF  [C0402]
C540  0.22UF  [C0402]
C541  0.22UF  [C0402]
C542  0.22UF  [C0402]
C543  0.22UF  [C0402]
C544  0.22UF  [C0402]
C545  0.22UF  [C0402]
C546  0.22UF  [C0402]
C547  0.22UF  [C0402]
C548  0.22UF  [C0402]
C549  0.22UF  [C0402]
C550  0.22UF  [C0402]
C551  0.22UF  [C0402]
C552  0.22UF  [C0402]
C553  0.22UF  [C0402]
C554  0.22UF  [C0402]
C555  0.22UF  [C0402]
C556  0.22UF  [C0402]
C557  0.22UF  [C0402]
C558  0.1UF  [C0402]
CE1  270UF  [EC83_248_390S]
CE2  330UF  [EC75_248_229S]
J3  PCIEX16  [G_PCI-E_X16_T2A]
R513  10K  [R0603]
R514  10K  [R0603]
R515  10K  [R0603]
R516  0  [R0603]
R517  0  [R0603]
R518  0  [R0603]
R519  0  [R0402]
R520  4.7K  [R0603]
sheet P32  PCIe x16 Slot-1
C559  10UF  [C0805_H61]
C560  1UF  [C0603]
C561  0.1UF  [C0402]
C562  0.1UF  [C0402]
C563  0.1UF  [C0402]
C564  0.1UF  [C0402]
C565  0.1UF  [C0402]
C566  10UF  [C1206_H76]
C567  0.1UF  [C0402]
C568  0.1UF  [C0402]
C569  22UF  [C0805_H61]
C570  0.22UF  [C0402]
C571  0.22UF  [C0402]
C572  0.22UF  [C0402]
C573  0.22UF  [C0402]
C574  0.22UF  [C0402]
C575  0.22UF  [C0402]
C576  0.22UF  [C0402]
C577  0.22UF  [C0402]
C578  0.22UF  [C0402]
C579  0.22UF  [C0402]
C580  0.22UF  [C0402]
C581  0.22UF  [C0402]
C582  0.22UF  [C0402]
C583  0.22UF  [C0402]
C584  0.22UF  [C0402]
C585  0.22UF  [C0402]
C586  0.22UF  [C0402]
C587  0.22UF  [C0402]
C588  0.22UF  [C0402]
C589  0.22UF  [C0402]
C590  0.22UF  [C0402]
C591  0.22UF  [C0402]
C592  0.22UF  [C0402]
C593  0.22UF  [C0402]
C594  0.22UF  [C0402]
C595  0.22UF  [C0402]
C596  0.22UF  [C0402]
C597  0.22UF  [C0402]
C598  0.22UF  [C0402]
C599  0.22UF  [C0402]
C600  0.22UF  [C0402]
C601  0.22UF  [C0402]
C602  0.1UF  [C0402]
CE3  270UF  [EC83_248_390S]
CE4  330UF  [EC75_248_229S]
J4  PCIEX16  [G_PCI-E_X16_T2A]
R521  10K  [R0603]
R522  10K  [R0603]
R523  10K  [R0603]
R524  0  [R0603]
R525  0  [R0603]
R526  0  [R0603]
R527  0  [R0402]
R528  4.7K  [R0603]

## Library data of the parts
C413 C424 C427 C428 C432 C443 C446 C447 C522 C560 = CAP_NP: Part_Type: *LF_C0603
C414 C422 C425 C433 C441 C444 C521 C525 C559 C569 = CAP_NP: Part_Type: *LF_C0805
C415-C421 C423 C426 C429-C431 C434-C440 C442 C445 C448-C519 C523 C524 C526-C558 C561-C565 C567 C568 C570-C602 C1373 = CAP_NP: Part_Type: *LF_C0402
L1-L4 = L: Part_Type: *LF_Inductor
Q21-Q24 Q42 Q43 = 2N7002DW: Part_Type: *LF_Semiconductor
R389 R390 R404 R411 R420 R429 R430 R435 R436 R446 R447 R457 R468 R477 R486 R487 R492 R493 R516-R518 R520 R524-R526 R528 = R: Part_Type: *LF_Resistor; WATTAGE: 1/10W
R391 R395 R396 R402 R425 R428 R431-R434 R448 R451 R459 R462 R482 R485 R488-R491 R509 R1196 R1197 R1199 R1200 R1212-R1215 = R: Not_insert: NI; Part_Type: *LF_Resistor; WATTAGE: 1/16W
R392-R394 R398 R399 R401 R403 R405-R410 R412 R414 R416 R418 R419 R423 R424 R426 R427 R438-R445 R449 R450 R454-R456 R458 R460 R461 R463-R467 R469 R471 R473 R475 R476 R480 R481 R483 R484 R495-R504 R506 R519 R527 R1093-R1116 R1181 R1198 R1201 R1202 R1211 = R: Part_Type: *LF_Resistor; WATTAGE: 1/16W
R397 R400 R413 R421 R422 R437 R452 R453 R470 R478 R479 R494 R513-R515 R521-R523 = R: Not_insert: NI; Part_Type: *LF_Resistor; WATTAGE: 1/10W
U5 U6 = 9FG830AFLFT: Part_Type: *LF_Chipset
Y1 Y2 = CRYSTAL: Part_Type: *LF_Misc
C1372 C1390 C1391 = CAP_NP: Part_Type: *LF_C0402; ROOM: VR_P1V05_PCH
J1 J2 J39 J40 = SCONN72_G40H2232212HRC: Part_Type: *LF_Connector
U107 U108 = 74LVC3G34: Part_Type: *LF_Chipset
U109 U111 = SN74LVC1G07: Part_Type: Chipset; Preference: TOSHIBA
C520 C566 = CAP_NP: Part_Type: *LF_C1206
CE1-CE4 = CAPACITOR_POL: Part_Type: *LF_C_ELEC_SMD
J3 = PCI_EXPRESS_X16_CONN: Part_Type: *LF_Connector
J4 = PCI_EXPRESS_X16_CONN: DIP_SMD: DIP; Part_Type: *LF_Connector

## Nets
GND: C413.2 C414.2 C415.2 C416.2 C417.2 C418.2 C419.2 C420.2 C421.2 C422.2 C423.2 C424.2 C425.2 C426.2 C427.1 C428.1 C429.2 C430.2 C431.2 C432.2 C433.2 C434.2 C435.2 C436.2 C437.2 C438.2 C439.2 C440.2 C441.2 C442.2 C443.2 C444.2 C445.2 C446.1 C447.1 C448.2 C449.2 C450.2 C515.2 C516.2 C517.2 C518.2 C519.2 C520.2 C521.2 C522.2 C523.2 C524.2 C525.2 C558.2 C559.2 C560.2 C561.2 C562.2 C563.2 C564.2 C565.2 C566.2 C567.2 C568.2 C569.2 C602.2 C1372.2 C1373.2 C1390.2 C1391.2 CE1.2 CE2.2 CE3.2 CE4.2 J1.A3(GND1) J1.A6(GND2) J1.A9(GND3) J1.A12(GND13) J1.A15(GND14) J1.A18(GND15) J1.B3(GND4) J1.B6(GND5) J1.B9(GND6) J1.B12(GND16) J1.B15(GND17) J1.B18(GND18) J1.C3(GND7) J1.C6(GND8) J1.C9(GND9) J1.C12(GND19) J1.C15(GND20) J1.C18(GND21) J1.D3(GND10) J1.D6(GND11) J1.D9(GND12) J1.D12(GND22) J1.D15(GND23) J1.D18(GND24) J1.G1 J1.G2 J1.G3 J1.G4 J1.G5 J1.G6 J2.A3(GND1) J2.A6(GND2) J2.A9(GND3) J2.A12(GND13) J2.A15(GND14) J2.A18(GND15) J2.B3(GND4) J2.B6(GND5) J2.B9(GND6) J2.B12(GND16) J2.B15(GND17) J2.B18(GND18) J2.C3(GND7) J2.C6(GND8) J2.C9(GND9) J2.C12(GND19) J2.C15(GND20) J2.C18(GND21) J2.D3(GND10) J2.D6(GND11) J2.D9(GND12) J2.D12(GND22) J2.D15(GND23) J2.D18(GND24) J2.G1 J2.G2 J2.G3 J2.G4 J2.G5 J2.G6 J3.A1(PRSNT1_N) J3.A4(GND35) J3.A12(GND36) J3.A15(GND37) J3.A18(GND38) J3.A20(GND39) J3.A23(GND40) J3.A24(GND41) J3.A27(GND42) J3.A28(GND43) J3.A31(GND44) J3.A34(GND45) J3.A37(GND46) J3.A38(GND47) J3.A41(GND48) J3.A42(GND49) J3.A45(GND50) J3.A46(GND51) J3.A49(GND52) J3.A51(GND53) J3.A54(GND54) J3.A55(GND55) J3.A58(GND56) J3.A59(GND57) J3.A62(GND58) J3.A63(GND59) J3.A66(GND60) J3.A67(RSVD8) J3.A70(GND61) J3.A71(GND62) J3.A74(GND63) J3.A75(GND64) J3.A78(GND65) J3.A79(GND66) J3.A82(GND67) J3.B4(GND1) J3.B7(GND2) J3.B13(GND3) J3.B16(GND4) J3.B18(GND5) J3.B21(GND6) J3.B22(GND7) J3.B25(GND8) J3.B26(GND9) J3.B29(GND10) J3.B32(GND11) J3.B35(GND12) J3.B36(GND13) J3.B39(GND14) J3.B40(GND15) J3.B43(GND16) J3.B44(GND17) J3.B47(GND18) J3.B49(GND19) J3.B52(GND20) J3.B53(GND21) J3.B56(GND22) J3.B57(GND23) J3.B60(GND24) J3.B61(GND25) J3.B64(GND26) J3.B65(GND27) J3.B68(GND28) J3.B69(GND29) J3.B72(GND30) J3.B73(GND31) J3.B76(GND32) J3.B77(GND33) J3.B80(GND34) J4.A1(PRSNT1_N) J4.A4(GND35) J4.A12(GND36) J4.A15(GND37) J4.A18(GND38) J4.A20(GND39) J4.A23(GND40) J4.A24(GND41) J4.A27(GND42) J4.A28(GND43) J4.A31(GND44) J4.A34(GND45) J4.A37(GND46) J4.A38(GND47) J4.A41(GND48) J4.A42(GND49) J4.A45(GND50) J4.A46(GND51) J4.A49(GND52) J4.A51(GND53) J4.A54(GND54) J4.A55(GND55) J4.A58(GND56) J4.A59(GND57) J4.A62(GND58) J4.A63(GND59) J4.A66(GND60) J4.A67(RSVD8) J4.A70(GND61) J4.A71(GND62) J4.A74(GND63) J4.A75(GND64) J4.A78(GND65) J4.A79(GND66) J4.A82(GND67) J4.B4(GND1) J4.B7(GND2) J4.B13(GND3) J4.B16(GND4) J4.B18(GND5) J4.B21(GND6) J4.B22(GND7) J4.B25(GND8) J4.B26(GND9) J4.B29(GND10) J4.B32(GND11) J4.B35(GND12) J4.B36(GND13) J4.B39(GND14) J4.B40(GND15) J4.B43(GND16) J4.B44(GND17) J4.B47(GND18) J4.B49(GND19) J4.B52(GND20) J4.B53(GND21) J4.B56(GND22) J4.B57(GND23) J4.B60(GND24) J4.B61(GND25) J4.B64(GND26) J4.B65(GND27) J4.B68(GND28) J4.B69(GND29) J4.B72(GND30) J4.B73(GND31) J4.B76(GND32) J4.B77(GND33) J4.B80(GND34) J39.A3(GND1) J39.A6(GND2) J39.A9(GND3) J39.A12(GND13) J39.A15(GND14) J39.A18(GND15) J39.B3(GND4) J39.B6(GND5) J39.B9(GND6) J39.B12(GND16) J39.B15(GND17) J39.B18(GND18) J39.C3(GND7) J39.C6(GND8) J39.C9(GND9) J39.C12(GND19) J39.C15(GND20) J39.C18(GND21) J39.D3(GND10) J39.D6(GND11) J39.D9(GND12) J39.D12(GND22) J39.D15(GND23) J39.D18(GND24) J39.G1 J39.G2 J39.G3 J39.G4 J39.G5 J39.G6 J40.A3(GND1) J40.A6(GND2) J40.A9(GND3) J40.A12(GND13) J40.A15(GND14) J40.A18(GND15) J40.B3(GND4) J40.B6(GND5) J40.B9(GND6) J40.B12(GND16) J40.B15(GND17) J40.B18(GND18) J40.C3(GND7) J40.C6(GND8) J40.C9(GND9) J40.C12(GND19) J40.C15(GND20) J40.C18(GND21) J40.D3(GND10) J40.D6(GND11) J40.D9(GND12) J40.D12(GND22) J40.D15(GND23) J40.D18(GND24) J40.G1 J40.G2 J40.G3 J40.G4 J40.G5 J40.G6 Q21.1(S1) Q21.4(S2) Q22.1(S1) Q22.4(S2) Q23.1(S1) Q23.4(S2) Q24.1(S1) Q24.4(S2) Q42.1(S1) Q42.4(S2) Q43.1(S1) Q43.4(S2) R394.1 R395.1 R400.2 R401.2 R402.1 R405.2 R408.2 R409.2 R412.2 R413.2 R414.2 R419.2 R420.2 R423.2 R427.2 R428.2 R432.2 R434.2 R435.1 R437.2 R453.2 R454.2 R456.2 R458.1 R459.1 R462.1 R463.2 R465.2 R469.2 R470.2 R471.2 R476.2 R477.2 R480.2 R484.2 R485.2 R489.2 R491.2 R492.1 R494.2 R1094.2 R1096.2 R1099.2 R1100.2 R1103.2 R1104.2 R1107.2 R1108.2 U5.4(GND) U5.15(GND) U5.35(GND) U5.47(GNDA) U6.4(GND) U6.15(GND) U6.35(GND) U6.47(GNDA) U107.4(GND) U107.6(3A) U108.4(GND) U108.6(3A) U109.3(GND) U111.3(GND) ; also on sheet 3 4 5 6 7 8 9 10 11 12 13 14 15 16 17 18 19 20 21 22 23 24 25 26 33 34 35 36 37 38 39 40 41 42 43 44 45 46 47 48 49 50 51 52 53 54 55 56 57 58 59 60 61 62 63 64 65 66 67
P3V3: C413.1 C424.1 C429.1 C430.1 C431.1 C432.1 C443.1 C448.1 C449.1 C450.1 C523.1 C524.1 C525.1 C567.1 C568.1 C569.1 CE2.1 CE4.1 J3.A9(3.3V_2) J3.A10(3.3V_3) J3.B8(3.3V_1) J4.A9(3.3V_2) J4.A10(3.3V_3) J4.B8(3.3V_1) L1.1 L2.1 L3.1 L4.1 R391.1 R396.1 R397.2 R404.2 R411.2 R425.2 R431.2 R433.2 R436.2 R438.2 R439.2 R440.2 R441.2 R448.1 R451.1 R452.2 R457.2 R468.2 R482.2 R488.2 R490.2 R493.2 R495.2 R496.2 R497.2 R498.2 R1109.2 R1110.2 R1113.2 R1114.2 ; also on sheet 10 22 33 34 35 36 37 38 41 44 51 53 59 60 61 62 63 64 65 66
P3V3_CLKA_VDD: C414.1 C415.1 C416.1 C417.1 C418.1 C419.1 C420.1 C421.1 L1.2 U5.10(VDD) U5.14(VDD) U5.19(VDD) U5.31(VDD) U5.36(VDD) U5.40(VDD)
P3V3_CLKA_VDDA: C425.1 C426.1 R390.2 U5.48(VDDA)
P3V3_CLKA_VDDR: C422.1 C423.1 R389.2 U5.3(VDD)
P3V3_CLKB_BUF_VDDA: L4.2 R446.1 R447.1
P3V3_CLKB_VDD: C433.1 C434.1 C435.1 C436.1 C437.1 C438.1 C439.1 C440.1 L3.2 U6.10(VDD) U6.14(VDD) U6.19(VDD) U6.31(VDD) U6.36(VDD) U6.40(VDD)
P3V3_CLKB_VDDA: C444.1 C445.1 R447.2 U6.48(VDDA)
P3V3_CLKB_VDDR: C441.1 C442.1 R446.2 U6.3(VDD)
P3V3_CLKBUF_VDDA: L2.2 R389.1 R390.1
P3V3_STBY: C521.1 C522.1 C559.1 C560.1 C1372.1 C1373.1 C1390.1 C1391.1 J3.B10(3.3VAUX) J4.B10(3.3VAUX) R421.1 R422.1 R478.1 R479.1 R513.1 R514.1 R515.1 R520.2 R521.1 R522.1 R523.1 R528.2 R1196.1 R1197.1 R1199.1 R1200.1 R1212.1 R1213.1 R1214.1 U107.8(VCC) U108.8(VCC) U109.5(VCC) U111.5(VCC) ; also on sheet 33 34 35 36 37 38 39 40 43 44 45 46 48 49 50 51 54 55 58 67
P12V_1: C515.1 C516.1 C517.1 C518.1 C519.1 C520.1 C561.1 C562.1 C563.1 C564.1 C565.1 C566.1 CE1.1 CE3.1 J3.A2(12V_4) J3.A3(12V_5) J3.B1(12V_1) J3.B2(12V_2) J3.B3(12V_3) J4.A2(12V_4) J4.A3(12V_5) J4.B1(12V_1) J4.B2(12V_2) J4.B3(12V_3) ; also on sheet 33 42 48 52 60 62 64
CLK_100M_NIC1_DN: R1093.2 R1094.1 ; also on sheet 39
CLK_100M_NIC1_DP: R1095.2 R1096.1 ; also on sheet 39
CLK_100M_NIC1_R_N: R1093.1 U5.21(DIF_4#)
CLK_100M_NIC1_R_P: R1095.1 U5.20(DIF_4)
CLK_100M_NIC2_DN: R1097.2 R1099.1 ; also on sheet 39
CLK_100M_NIC2_DP: R1098.2 R1100.1 ; also on sheet 39
CLK_100M_NIC2_R_N: R1097.1 U5.18(DIF_5#)
CLK_100M_NIC2_R_P: R1098.1 U5.17(DIF_5)
CLK_100M_NIC3_DN: R1101.2 R1103.1 ; also on sheet 40
CLK_100M_NIC3_DP: R1102.2 R1104.1 ; also on sheet 40
CLK_100M_NIC4_DN: R1105.2 R1107.1 ; also on sheet 40
CLK_100M_NIC4_DP: R1106.2 R1108.1 ; also on sheet 40
CLK_100M_PE0_N: J3.A14(REFCLK-) R418.2 R419.1
CLK_100M_PE0_P: J3.A13(REFCLK+) R414.1 R416.2
CLK_100M_PE0_R_N: R418.1 U5.29(DIF_3#)
CLK_100M_PE0_R_P: R416.1 U5.30(DIF_3)
CLK_100M_PE1_N: J4.A14(REFCLK-) R410.2 R412.1
CLK_100M_PE1_P: J4.A13(REFCLK+) R403.2 R409.1
CLK_100M_PE1_R_N: R410.1 U5.32(DIF_2#)
CLK_100M_PE1_R_P: R403.1 U5.33(DIF_2)
CLK_100M_PE2_N: R407.2 R408.1 ; also on sheet 33
CLK_100M_PE2_P: R405.1 R406.2 ; also on sheet 33
CLK_100M_PE2_R_N: R407.1 U5.38(DIF_1#)
CLK_100M_PE2_R_P: R406.1 U5.39(DIF_1)
CLK_100M_PE3_N: R426.2 R427.1 ; also on sheet 34
CLK_100M_PE3_P: R423.1 R424.2 ; also on sheet 34
CLK_100M_PE3_R_N: R426.1 U5.12(DIF_6#)
CLK_100M_PE3_R_P: R424.1 U5.11(DIF_6)
CLK_100M_PE4_N: R475.2 R476.1 ; also on sheet 35
CLK_100M_PE4_P: R471.1 R473.2 ; also on sheet 35
CLK_100M_PE4_R_N: R475.1 U6.29(DIF_3#)
CLK_100M_PE4_R_P: R473.1 U6.30(DIF_3)
CLK_100M_PE5_N: R467.2 R469.1 ; also on sheet 36
CLK_100M_PE5_P: R456.1 R466.2 ; also on sheet 36
CLK_100M_PE5_R_N: R467.1 U6.32(DIF_2#)
CLK_100M_PE5_R_P: R466.1 U6.33(DIF_2)
CLK_100M_PE6_N: R464.2 R465.1 ; also on sheet 37
CLK_100M_PE6_P: R455.2 R463.1 ; also on sheet 37
CLK_100M_PE6_R_N: R464.1 U6.38(DIF_1#)
CLK_100M_PE6_R_P: R455.1 U6.39(DIF_1)
CLK_100M_PE7_N: R483.2 R484.1 ; also on sheet 38
CLK_100M_PE7_P: R480.1 R481.2 ; also on sheet 38
CLK_100M_PE7_R_N: R483.1 U6.12(DIF_6#)
CLK_100M_PE7_R_P: R481.1 U6.11(DIF_6)
CLK_100M_PLX1_PEXREF_CN: R398.2 R399.1 R401.1
CLK_100M_PLX1_PEXREF_CP: R392.2 R393.1 R394.2
CLK_100M_PLX1_PEXREF_N: R396.2 R399.2 R402.2 ; also on sheet 3
CLK_100M_PLX1_PEXREF_P: R391.2 R393.2 R395.2 ; also on sheet 3
CLK_100M_PLX1_PEXREF_RN: R398.1 U5.41(DIF_0#)
CLK_100M_PLX1_PEXREF_RP: R392.1 U5.42(DIF_0)
CLK_100M_PLX2_PEXREF_CN: R454.1 R460.2 R461.1
CLK_100M_PLX2_PEXREF_CP: R449.2 R450.1 R458.2
CLK_100M_PLX2_PEXREF_N: R451.2 R461.2 R462.2 ; also on sheet 15
CLK_100M_PLX2_PEXREF_P: R448.2 R450.2 R459.2 ; also on sheet 15
CLK_100M_PLX2_PEXREF_RN: R460.1 U6.41(DIF_0#)
CLK_100M_PLX2_PEXREF_RP: R449.1 U6.42(DIF_0)
CLK_DIF_STOP: R436.1 R437.1 U5.25(DIF_STOP#)
CLK_IN_9FG830A: C427.2 U5.1(XIN|CLKIN) Y1.2
CLK_OUT_9FG830A: C428.2 U5.2(X2) Y1.1
CLKB_100M_NIC3_R_N: R1101.1 U6.21(DIF_4#)
CLKB_100M_NIC3_R_P: R1102.1 U6.20(DIF_4)
CLKB_100M_NIC4_R_N: R1105.1 U6.18(DIF_5#)
CLKB_100M_NIC4_R_P: R1106.1 U6.17(DIF_5)
CLKB_DIF_STOP_N: R493.1 R494.1 U6.25(DIF_STOP#)
CLKB_IN_9FG830A: C446.2 U6.1(XIN|CLKIN) Y2.2
CLKB_OUT_9FG830A: C447.2 U6.2(X2) Y2.1
CLKBEN_NIC3_R: Q43.6(D1) R1115.2
CLKBEN_NIC4_R: Q43.3(D2) R1116.1
CLKBEN_PE0: R495.1 R499.1 U6.28(vOE_3)
CLKBEN_PE0_R: Q23.6(D1) R499.2
CLKBEN_PE1: R496.1 R500.2 U6.34(^OE_2)
CLKBEN_PE1_R: Q23.3(D2) R500.1
CLKBEN_PE2: R497.1 R501.1 U6.37(^OE_1)
CLKBEN_PE2_R: Q24.6(D1) R501.2
CLKBEN_PE3: R498.1 R502.2 U6.13(^OE_6)
CLKBEN_PE3_R: Q24.3(D2) R502.1
CLKBUF_B_IREF: R492.2 U6.46(IREF)
CLKBUF_IREF: R435.2 U5.46(IREF)
CLKEN_NIC1: R1109.1 R1111.1 U5.22(vOE_4)
CLKEN_NIC1_R: Q42.6(D1) R1111.2
CLKEN_NIC2: R1110.1 R1112.2 U5.16(^OE_5)
CLKEN_NIC2_R: Q42.3(D2) R1112.1
CLKEN_NIC3: R1113.1 R1115.1 U6.22(vOE_4)
CLKEN_NIC4: R1114.1 R1116.2 U6.16(^OE_5)
CLKEN_PE0: R438.1 R442.1 U5.28(vOE_3)
CLKEN_PE0_R: Q21.6(D1) R442.2
CLKEN_PE1: R439.1 R443.2 U5.34(^OE_2)
CLKEN_PE1_R: Q21.3(D2) R443.1
CLKEN_PE2: R440.1 R444.1 U5.37(^OE_1)
CLKEN_PE2_R: Q22.6(D1) R444.2
CLKEN_PE3: R441.1 R445.2 U5.13(^OE_6)
CLKEN_PE3_R: Q22.3(D2) R445.1
GPU_THROTTLE_IPASS_A_R_N: J1.B2(SB1) R504.2
GPU_THROTTLE_IPASS_B_R_N: J39.B2(SB1) R509.2
GPU_THROTTLE_N: R504.1 R509.1 ; also on sheet 67
GPU_THROTTLE_SLOT0_N: R519.1 ; also on sheet 67
GPU_THROTTLE_SLOT0_R_N: J3.B12(RSVD1) R515.2 R519.2
GPU_THROTTLE_SLOT1_N: R527.1 ; also on sheet 67
GPU_THROTTLE_SLOT1_R_N: J4.B12(RSVD1) R523.2 R527.2
NIC1_PRESET_N: Q42.2(G1) ; also on sheet 39
NIC2_PRESET_N: Q42.5(G2) ; also on sheet 39
NIC3_PRESET_N: Q43.2(G1) ; also on sheet 40
NIC4_PRESET_N: Q43.5(G2) ; also on sheet 40
PCIE_WAKE_NIC1_N: R1212.2 U109.2(A) ; also on sheet 39
PCIE_WAKE_NIC3_N: R1213.2 U111.2(A) ; also on sheet 40
PCIE_WAKE_NIC_A_N: J1.C1(SB4) R1211.1
PCIE_WAKE_NIC_C_N: J39.C1(SB4) R1215.1
PCIE_WAKE_NIC_R_N: R1211.2 R1214.2 R1215.2 U109.4(Y) U111.4(Y)
PD_9FG830A_B_SS: R452.1 R453.1 U6.26(vSPREAD)
PD_9FG830A_SS: R397.1 R400.1 U5.26(vSPREAD)
PD_CLK_OE_7: R420.1 U5.7(vOE)
PD_CLKB_OE_7: R477.1 U6.7(vOE)
PE_SLOT0_PRSNT_N: C558.1 J3.B17(PRSNT2_N-1) J3.B31(PRSNT2_N-2) J3.B48(PRSNT2_N-3) J3.B81(PRSNT2_N-4) Q21.2(G1) R520.1
PE_SLOT1_PRSNT_N: C602.1 J4.B17(PRSNT2_N-1) J4.B31(PRSNT2_N-2) J4.B48(PRSNT2_N-3) J4.B81(PRSNT2_N-4) Q21.5(G2) R528.1
PE_SLOT2_PRSNT_N: Q22.2(G1) ; also on sheet 33
PE_SLOT3_PRSNT_N: Q22.5(G2) ; also on sheet 34
PE_SLOT4_PRSNT_N: Q23.2(G1) ; also on sheet 35
PE_SLOT5_PRSNT_N: Q23.5(G2) ; also on sheet 36
PE_SLOT6_PRSNT_N: Q24.2(G1) ; also on sheet 37
PE_SLOT7_PRSNT_N: Q24.5(G2) ; also on sheet 38
PEX_IPASS_A_RXN0: J1.D5(TX0-) ; also on sheet 3
PEX_IPASS_A_RXN1: J1.C5(TX1-) ; also on sheet 3
PEX_IPASS_A_RXN2: J1.D8(TX2-) ; also on sheet 3
PEX_IPASS_A_RXN3: J1.C8(TX3-) ; also on sheet 3
PEX_IPASS_A_RXN4: J1.D14(TX4-) ; also on sheet 3
PEX_IPASS_A_RXN5: J1.C14(TX5-) ; also on sheet 3
PEX_IPASS_A_RXN6: J1.D17(TX6-) ; also on sheet 3
PEX_IPASS_A_RXN7: J1.C17(TX7-) ; also on sheet 3
PEX_IPASS_A_RXN8: J2.D5(TX0-) ; also on sheet 3
PEX_IPASS_A_RXN9: J2.C5(TX1-) ; also on sheet 3
PEX_IPASS_A_RXN10: J2.D8(TX2-) ; also on sheet 3
PEX_IPASS_A_RXN11: J2.C8(TX3-) ; also on sheet 3
PEX_IPASS_A_RXN12: J2.D14(TX4-) ; also on sheet 3
PEX_IPASS_A_RXN13: J2.C14(TX5-) ; also on sheet 3
PEX_IPASS_A_RXN14: J2.D17(TX6-) ; also on sheet 3
PEX_IPASS_A_RXN15: J2.C17(TX7-) ; also on sheet 3
PEX_IPASS_A_RXP0: J1.D4(TX0+) ; also on sheet 3
PEX_IPASS_A_RXP1: J1.C4(TX1+) ; also on sheet 3
PEX_IPASS_A_RXP2: J1.D7(TX2+) ; also on sheet 3
PEX_IPASS_A_RXP3: J1.C7(TX3+) ; also on sheet 3
PEX_IPASS_A_RXP4: J1.D13(TX4+) ; also on sheet 3
PEX_IPASS_A_RXP5: J1.C13(TX5+) ; also on sheet 3
PEX_IPASS_A_RXP6: J1.D16(TX6+) ; also on sheet 3
PEX_IPASS_A_RXP7: J1.C16(TX7+) ; also on sheet 3
PEX_IPASS_A_RXP8: J2.D4(TX0+) ; also on sheet 3
PEX_IPASS_A_RXP9: J2.C4(TX1+) ; also on sheet 3
PEX_IPASS_A_RXP10: J2.D7(TX2+) ; also on sheet 3
PEX_IPASS_A_RXP11: J2.C7(TX3+) ; also on sheet 3
PEX_IPASS_A_RXP12: J2.D13(TX4+) ; also on sheet 3
PEX_IPASS_A_RXP13: J2.C13(TX5+) ; also on sheet 3
PEX_IPASS_A_RXP14: J2.D16(TX6+) ; also on sheet 3
PEX_IPASS_A_RXP15: J2.C16(TX7+) ; also on sheet 3
PEX_IPASS_A_TXN0: C482.1 ; also on sheet 3
PEX_IPASS_A_TXN0_C: C482.2 J1.B5(RX0-)
PEX_IPASS_A_TXN1: C480.1 ; also on sheet 3
PEX_IPASS_A_TXN1_C: C480.2 J1.A5(RX1-)
PEX_IPASS_A_TXN2: C478.1 ; also on sheet 3
PEX_IPASS_A_TXN2_C: C478.2 J1.B8(RX2-)
PEX_IPASS_A_TXN3: C476.1 ; also on sheet 3
PEX_IPASS_A_TXN3_C: C476.2 J1.A8(RX3-)
PEX_IPASS_A_TXN4: C474.1 ; also on sheet 3
PEX_IPASS_A_TXN4_C: C474.2 J1.B14(RX4-)
PEX_IPASS_A_TXN5: C472.1 ; also on sheet 3
PEX_IPASS_A_TXN5_C: C472.2 J1.A14(RX5-)
PEX_IPASS_A_TXN6: C470.1 ; also on sheet 3
PEX_IPASS_A_TXN6_C: C470.2 J1.B17(RX6-)
PEX_IPASS_A_TXN7: C467.1 ; also on sheet 3
PEX_IPASS_A_TXN7_C: C467.2 J1.A17(RX7-)
PEX_IPASS_A_TXN8: C466.1 ; also on sheet 3
PEX_IPASS_A_TXN8_C: C466.2 J2.B5(RX0-)
PEX_IPASS_A_TXN9: C464.1 ; also on sheet 3
PEX_IPASS_A_TXN9_C: C464.2 J2.A5(RX1-)
PEX_IPASS_A_TXN10: C462.1 ; also on sheet 3
PEX_IPASS_A_TXN10_C: C462.2 J2.B8(RX2-)
PEX_IPASS_A_TXN11: C460.1 ; also on sheet 3
PEX_IPASS_A_TXN11_C: C460.2 J2.A8(RX3-)
PEX_IPASS_A_TXN12: C458.1 ; also on sheet 3
PEX_IPASS_A_TXN12_C: C458.2 J2.B14(RX4-)
PEX_IPASS_A_TXN13: C456.1 ; also on sheet 3
PEX_IPASS_A_TXN13_C: C456.2 J2.A14(RX5-)
PEX_IPASS_A_TXN14: C454.1 ; also on sheet 3
PEX_IPASS_A_TXN14_C: C454.2 J2.B17(RX6-)
PEX_IPASS_A_TXN15: C452.1 ; also on sheet 3
PEX_IPASS_A_TXN15_C: C452.2 J2.A17(RX7-)
PEX_IPASS_A_TXP0: C481.1 ; also on sheet 3
PEX_IPASS_A_TXP0_C: C481.2 J1.B4(RX0+)
PEX_IPASS_A_TXP1: C479.1 ; also on sheet 3
PEX_IPASS_A_TXP1_C: C479.2 J1.A4(RX1+)
PEX_IPASS_A_TXP2: C477.1 ; also on sheet 3
PEX_IPASS_A_TXP2_C: C477.2 J1.B7(RX2+)
PEX_IPASS_A_TXP3: C475.1 ; also on sheet 3
PEX_IPASS_A_TXP3_C: C475.2 J1.A7(RX3+)
PEX_IPASS_A_TXP4: C473.1 ; also on sheet 3
PEX_IPASS_A_TXP4_C: C473.2 J1.B13(RX4+)
PEX_IPASS_A_TXP5: C471.1 ; also on sheet 3
PEX_IPASS_A_TXP5_C: C471.2 J1.A13(RX5+)
PEX_IPASS_A_TXP6: C469.1 ; also on sheet 3
PEX_IPASS_A_TXP6_C: C469.2 J1.B16(RX6+)
PEX_IPASS_A_TXP7: C468.1 ; also on sheet 3
PEX_IPASS_A_TXP7_C: C468.2 J1.A16(RX7+)
PEX_IPASS_A_TXP8: C465.1 ; also on sheet 3
PEX_IPASS_A_TXP8_C: C465.2 J2.B4(RX0+)
PEX_IPASS_A_TXP9: C463.1 ; also on sheet 3
PEX_IPASS_A_TXP9_C: C463.2 J2.A4(RX1+)
PEX_IPASS_A_TXP10: C461.1 ; also on sheet 3
PEX_IPASS_A_TXP10_C: C461.2 J2.B7(RX2+)
PEX_IPASS_A_TXP11: C459.1 ; also on sheet 3
PEX_IPASS_A_TXP11_C: C459.2 J2.A7(RX3+)
PEX_IPASS_A_TXP12: C457.1 ; also on sheet 3
PEX_IPASS_A_TXP12_C: C457.2 J2.B13(RX4+)
PEX_IPASS_A_TXP13: C455.1 ; also on sheet 3
PEX_IPASS_A_TXP13_C: C455.2 J2.A13(RX5+)
PEX_IPASS_A_TXP14: C453.1 ; also on sheet 3
PEX_IPASS_A_TXP14_C: C453.2 J2.B16(RX6+)
PEX_IPASS_A_TXP15: C451.1 ; also on sheet 3
PEX_IPASS_A_TXP15_C: C451.2 J2.A16(RX7+)
PEX_IPASS_B_RXN0: J39.D5(TX0-) ; also on sheet 15
PEX_IPASS_B_RXN1: J39.C5(TX1-) ; also on sheet 15
PEX_IPASS_B_RXN2: J39.D8(TX2-) ; also on sheet 15
PEX_IPASS_B_RXN3: J39.C8(TX3-) ; also on sheet 15
PEX_IPASS_B_RXN4: J39.D14(TX4-) ; also on sheet 15
PEX_IPASS_B_RXN5: J39.C14(TX5-) ; also on sheet 15
PEX_IPASS_B_RXN6: J39.D17(TX6-) ; also on sheet 15
PEX_IPASS_B_RXN7: J39.C17(TX7-) ; also on sheet 15
PEX_IPASS_B_RXN8: J40.D5(TX0-) ; also on sheet 15
PEX_IPASS_B_RXN9: J40.C5(TX1-) ; also on sheet 15
PEX_IPASS_B_RXN10: J40.D8(TX2-) ; also on sheet 15
PEX_IPASS_B_RXN11: J40.C8(TX3-) ; also on sheet 15
PEX_IPASS_B_RXN12: J40.D14(TX4-) ; also on sheet 15
PEX_IPASS_B_RXN13: J40.C14(TX5-) ; also on sheet 15
PEX_IPASS_B_RXN14: J40.D17(TX6-) ; also on sheet 15
PEX_IPASS_B_RXN15: J40.C17(TX7-) ; also on sheet 15
PEX_IPASS_B_RXP0: J39.D4(TX0+) ; also on sheet 15
PEX_IPASS_B_RXP1: J39.C4(TX1+) ; also on sheet 15
PEX_IPASS_B_RXP2: J39.D7(TX2+) ; also on sheet 15
PEX_IPASS_B_RXP3: J39.C7(TX3+) ; also on sheet 15
PEX_IPASS_B_RXP4: J39.D13(TX4+) ; also on sheet 15
PEX_IPASS_B_RXP5: J39.C13(TX5+) ; also on sheet 15
PEX_IPASS_B_RXP6: J39.D16(TX6+) ; also on sheet 15
PEX_IPASS_B_RXP7: J39.C16(TX7+) ; also on sheet 15
PEX_IPASS_B_RXP8: J40.D4(TX0+) ; also on sheet 15
PEX_IPASS_B_RXP9: J40.C4(TX1+) ; also on sheet 15
PEX_IPASS_B_RXP10: J40.D7(TX2+) ; also on sheet 15
PEX_IPASS_B_RXP11: J40.C7(TX3+) ; also on sheet 15
PEX_IPASS_B_RXP12: J40.D13(TX4+) ; also on sheet 15
PEX_IPASS_B_RXP13: J40.C13(TX5+) ; also on sheet 15
PEX_IPASS_B_RXP14: J40.D16(TX6+) ; also on sheet 15
PEX_IPASS_B_RXP15: J40.C16(TX7+) ; also on sheet 15
PEX_IPASS_B_TXN0: C514.1 ; also on sheet 15
PEX_IPASS_B_TXN0_C: C514.2 J39.B5(RX0-)
PEX_IPASS_B_TXN1: C512.1 ; also on sheet 15
PEX_IPASS_B_TXN1_C: C512.2 J39.A5(RX1-)
PEX_IPASS_B_TXN2: C510.1 ; also on sheet 15
PEX_IPASS_B_TXN2_C: C510.2 J39.B8(RX2-)
PEX_IPASS_B_TXN3: C508.1 ; also on sheet 15
PEX_IPASS_B_TXN3_C: C508.2 J39.A8(RX3-)
PEX_IPASS_B_TXN4: C506.1 ; also on sheet 15
PEX_IPASS_B_TXN4_C: C506.2 J39.B14(RX4-)
PEX_IPASS_B_TXN5: C504.1 ; also on sheet 15
PEX_IPASS_B_TXN5_C: C504.2 J39.A14(RX5-)
PEX_IPASS_B_TXN6: C502.1 ; also on sheet 15
PEX_IPASS_B_TXN6_C: C502.2 J39.B17(RX6-)
PEX_IPASS_B_TXN7: C500.1 ; also on sheet 15
PEX_IPASS_B_TXN7_C: C500.2 J39.A17(RX7-)
PEX_IPASS_B_TXN8: C498.1 ; also on sheet 15
PEX_IPASS_B_TXN8_C: C498.2 J40.B5(RX0-)
PEX_IPASS_B_TXN9: C496.1 ; also on sheet 15
PEX_IPASS_B_TXN9_C: C496.2 J40.A5(RX1-)
PEX_IPASS_B_TXN10: C494.1 ; also on sheet 15
PEX_IPASS_B_TXN10_C: C494.2 J40.B8(RX2-)
PEX_IPASS_B_TXN11: C492.1 ; also on sheet 15
PEX_IPASS_B_TXN11_C: C492.2 J40.A8(RX3-)
PEX_IPASS_B_TXN12: C490.1 ; also on sheet 15
PEX_IPASS_B_TXN12_C: C490.2 J40.B14(RX4-)
PEX_IPASS_B_TXN13: C488.1 ; also on sheet 15
PEX_IPASS_B_TXN13_C: C488.2 J40.A14(RX5-)
PEX_IPASS_B_TXN14: C486.1 ; also on sheet 15
PEX_IPASS_B_TXN14_C: C486.2 J40.B17(RX6-)
PEX_IPASS_B_TXN15: C484.1 ; also on sheet 15
PEX_IPASS_B_TXN15_C: C484.2 J40.A17(RX7-)
PEX_IPASS_B_TXP0: C513.1 ; also on sheet 15
PEX_IPASS_B_TXP0_C: C513.2 J39.B4(RX0+)
PEX_IPASS_B_TXP1: C511.1 ; also on sheet 15
PEX_IPASS_B_TXP1_C: C511.2 J39.A4(RX1+)
PEX_IPASS_B_TXP2: C509.1 ; also on sheet 15
PEX_IPASS_B_TXP2_C: C509.2 J39.B7(RX2+)
PEX_IPASS_B_TXP3: C507.1 ; also on sheet 15
PEX_IPASS_B_TXP3_C: C507.2 J39.A7(RX3+)
PEX_IPASS_B_TXP4: C505.1 ; also on sheet 15
PEX_IPASS_B_TXP4_C: C505.2 J39.B13(RX4+)
PEX_IPASS_B_TXP5: C503.1 ; also on sheet 15
PEX_IPASS_B_TXP5_C: C503.2 J39.A13(RX5+)
PEX_IPASS_B_TXP6: C501.1 ; also on sheet 15
PEX_IPASS_B_TXP6_C: C501.2 J39.B16(RX6+)
PEX_IPASS_B_TXP7: C499.1 ; also on sheet 15
PEX_IPASS_B_TXP7_C: C499.2 J39.A16(RX7+)
PEX_IPASS_B_TXP8: C497.1 ; also on sheet 15
PEX_IPASS_B_TXP8_C: C497.2 J40.B4(RX0+)
PEX_IPASS_B_TXP9: C495.1 ; also on sheet 15
PEX_IPASS_B_TXP9_C: C495.2 J40.A4(RX1+)
PEX_IPASS_B_TXP10: C493.1 ; also on sheet 15
PEX_IPASS_B_TXP10_C: C493.2 J40.B7(RX2+)
PEX_IPASS_B_TXP11: C491.1 ; also on sheet 15
PEX_IPASS_B_TXP11_C: C491.2 J40.A7(RX3+)
PEX_IPASS_B_TXP12: C489.1 ; also on sheet 15
PEX_IPASS_B_TXP12_C: C489.2 J40.B13(RX4+)
PEX_IPASS_B_TXP13: C487.1 ; also on sheet 15
PEX_IPASS_B_TXP13_C: C487.2 J40.A13(RX5+)
PEX_IPASS_B_TXP14: C485.1 ; also on sheet 15
PEX_IPASS_B_TXP14_C: C485.2 J40.B16(RX6+)
PEX_IPASS_B_TXP15: C483.1 ; also on sheet 15
PEX_IPASS_B_TXP15_C: C483.2 J40.A16(RX7+)
PEX_PE0_RXN0: J3.A17(HSIP0-) ; also on sheet 5
PEX_PE0_RXN1: J3.A22(HSIP1-) ; also on sheet 5
PEX_PE0_RXN2: J3.A26(HSIP2-) ; also on sheet 5
PEX_PE0_RXN3: J3.A30(HSIP3-) ; also on sheet 5
PEX_PE0_RXN4: J3.A36(HSIP4-) ; also on sheet 5
PEX_PE0_RXN5: J3.A40(HSIP5-) ; also on sheet 5
PEX_PE0_RXN6: J3.A44(HSIP6-) ; also on sheet 5
PEX_PE0_RXN7: J3.A48(HSIP7-) ; also on sheet 5
PEX_PE0_RXN8: J3.A53(HSIP8-) ; also on sheet 5
PEX_PE0_RXN9: J3.A57(HSIP9-) ; also on sheet 5
PEX_PE0_RXN10: J3.A61(HSIP10-) ; also on sheet 5
PEX_PE0_RXN11: J3.A65(HSIP11-) ; also on sheet 5
PEX_PE0_RXN12: J3.A69(HSIP12-) ; also on sheet 5
PEX_PE0_RXN13: J3.A73(HSIP13-) ; also on sheet 5
PEX_PE0_RXN14: J3.A77(HSIP14-) ; also on sheet 5
PEX_PE0_RXN15: J3.A81(HSIP15-) ; also on sheet 5
PEX_PE0_RXP0: J3.A16(HSIP0+) ; also on sheet 5
PEX_PE0_RXP1: J3.A21(HSIP1+) ; also on sheet 5
PEX_PE0_RXP2: J3.A25(HSIP2+) ; also on sheet 5
PEX_PE0_RXP3: J3.A29(HSIP3+) ; also on sheet 5
PEX_PE0_RXP4: J3.A35(HSIP4+) ; also on sheet 5
PEX_PE0_RXP5: J3.A39(HSIP5+) ; also on sheet 5
PEX_PE0_RXP6: J3.A43(HSIP6+) ; also on sheet 5
PEX_PE0_RXP7: J3.A47(HSIP7+) ; also on sheet 5
PEX_PE0_RXP8: J3.A52(HSIP8+) ; also on sheet 5
PEX_PE0_RXP9: J3.A56(HSIP9+) ; also on sheet 5
PEX_PE0_RXP10: J3.A60(HSIP10+) ; also on sheet 5
PEX_PE0_RXP11: J3.A64(HSIP11+) ; also on sheet 5
PEX_PE0_RXP12: J3.A68(HSIP12+) ; also on sheet 5
PEX_PE0_RXP13: J3.A72(HSIP13+) ; also on sheet 5
PEX_PE0_RXP14: J3.A76(HSIP14) ; also on sheet 5
PEX_PE0_RXP15: J3.A80(HSIP15+) ; also on sheet 5
PEX_PE0_TXN0: C527.1 ; also on sheet 5
PEX_PE0_TXN0_C: C527.2 J3.B15(HSOP0-)
PEX_PE0_TXN1: C529.1 ; also on sheet 5
PEX_PE0_TXN1_C: C529.2 J3.B20(HSOP1-)
PEX_PE0_TXN2: C531.1 ; also on sheet 5
PEX_PE0_TXN2_C: C531.2 J3.B24(HSOP2-)
PEX_PE0_TXN3: C533.1 ; also on sheet 5
PEX_PE0_TXN3_C: C533.2 J3.B28(HSOP3-)
PEX_PE0_TXN4: C535.1 ; also on sheet 5
PEX_PE0_TXN4_C: C535.2 J3.B34(HSOP4-)
PEX_PE0_TXN5: C537.1 ; also on sheet 5
PEX_PE0_TXN5_C: C537.2 J3.B38(HSOP5-)
PEX_PE0_TXN6: C539.1 ; also on sheet 5
PEX_PE0_TXN6_C: C539.2 J3.B42(HSOP6-)
PEX_PE0_TXN7: C541.1 ; also on sheet 5
PEX_PE0_TXN7_C: C541.2 J3.B46(HSOP7-)
PEX_PE0_TXN8: C543.1 ; also on sheet 5
PEX_PE0_TXN8_C: C543.2 J3.B51(HSOP8-)
PEX_PE0_TXN9: C545.1 ; also on sheet 5
PEX_PE0_TXN9_C: C545.2 J3.B55(HSOP9-)
PEX_PE0_TXN10: C547.1 ; also on sheet 5
PEX_PE0_TXN10_C: C547.2 J3.B59(HSOP10-)
PEX_PE0_TXN11: C549.1 ; also on sheet 5
PEX_PE0_TXN11_C: C549.2 J3.B63(HSOP11-)
PEX_PE0_TXN12: C551.1 ; also on sheet 5
PEX_PE0_TXN12_C: C551.2 J3.B67(HSOP12-)
PEX_PE0_TXN13: C553.1 ; also on sheet 5
PEX_PE0_TXN13_C: C553.2 J3.B71(HSOP13-)
PEX_PE0_TXN14: C555.1 ; also on sheet 5
PEX_PE0_TXN14_C: C555.2 J3.B75(HSOP14-)
PEX_PE0_TXN15: C557.1 ; also on sheet 5
PEX_PE0_TXN15_C: C557.2 J3.B79(HSOP15-)
PEX_PE0_TXP0: C526.1 ; also on sheet 5
PEX_PE0_TXP0_C: C526.2 J3.B14(HSOP0+)
PEX_PE0_TXP1: C528.1 ; also on sheet 5
PEX_PE0_TXP1_C: C528.2 J3.B19(HSOP1+)
PEX_PE0_TXP2: C530.1 ; also on sheet 5
PEX_PE0_TXP2_C: C530.2 J3.B23(HSOP2+)
PEX_PE0_TXP3: C532.1 ; also on sheet 5
PEX_PE0_TXP3_C: C532.2 J3.B27(HSOP3+)
PEX_PE0_TXP4: C534.1 ; also on sheet 5
PEX_PE0_TXP4_C: C534.2 J3.B33(HSOP4+)
PEX_PE0_TXP5: C536.1 ; also on sheet 5
PEX_PE0_TXP5_C: C536.2 J3.B37(HSOP5+)
PEX_PE0_TXP6: C538.1 ; also on sheet 5
PEX_PE0_TXP6_C: C538.2 J3.B41(HSOP6+)
PEX_PE0_TXP7: C540.1 ; also on sheet 5
PEX_PE0_TXP7_C: C540.2 J3.B45(HSOP7+)
PEX_PE0_TXP8: C542.1 ; also on sheet 5
PEX_PE0_TXP8_C: C542.2 J3.B50(HSOP8+)
PEX_PE0_TXP9: C544.1 ; also on sheet 5
PEX_PE0_TXP9_C: C544.2 J3.B54(HSOP9+)
PEX_PE0_TXP10: C546.1 ; also on sheet 5
PEX_PE0_TXP10_C: C546.2 J3.B58(HSOP10+)
PEX_PE0_TXP11: C548.1 ; also on sheet 5
PEX_PE0_TXP11_C: C548.2 J3.B62(HSOP11+)
PEX_PE0_TXP12: C550.1 ; also on sheet 5
PEX_PE0_TXP12_C: C550.2 J3.B66(HSOP12+)
PEX_PE0_TXP13: C552.1 ; also on sheet 5
PEX_PE0_TXP13_C: C552.2 J3.B70(HSOP13+)
PEX_PE0_TXP14: C554.1 ; also on sheet 5
PEX_PE0_TXP14_C: C554.2 J3.B74(HSOP14+)
PEX_PE0_TXP15: C556.1 ; also on sheet 5
PEX_PE0_TXP15_C: C556.2 J3.B78(HSOP15+)
PEX_PE1_RXN0: J4.A17(HSIP0-) ; also on sheet 7
PEX_PE1_RXN1: J4.A22(HSIP1-) ; also on sheet 7
PEX_PE1_RXN2: J4.A26(HSIP2-) ; also on sheet 7
PEX_PE1_RXN3: J4.A30(HSIP3-) ; also on sheet 7
PEX_PE1_RXN4: J4.A36(HSIP4-) ; also on sheet 7
PEX_PE1_RXN5: J4.A40(HSIP5-) ; also on sheet 7
PEX_PE1_RXN6: J4.A44(HSIP6-) ; also on sheet 7
PEX_PE1_RXN7: J4.A48(HSIP7-) ; also on sheet 7
PEX_PE1_RXN8: J4.A53(HSIP8-) ; also on sheet 7
PEX_PE1_RXN9: J4.A57(HSIP9-) ; also on sheet 7
PEX_PE1_RXN10: J4.A61(HSIP10-) ; also on sheet 7
PEX_PE1_RXN11: J4.A65(HSIP11-) ; also on sheet 7
PEX_PE1_RXN12: J4.A69(HSIP12-) ; also on sheet 7
PEX_PE1_RXN13: J4.A73(HSIP13-) ; also on sheet 7
PEX_PE1_RXN14: J4.A77(HSIP14-) ; also on sheet 7
PEX_PE1_RXN15: J4.A81(HSIP15-) ; also on sheet 7
PEX_PE1_RXP0: J4.A16(HSIP0+) ; also on sheet 7
PEX_PE1_RXP1: J4.A21(HSIP1+) ; also on sheet 7
PEX_PE1_RXP2: J4.A25(HSIP2+) ; also on sheet 7
PEX_PE1_RXP3: J4.A29(HSIP3+) ; also on sheet 7
PEX_PE1_RXP4: J4.A35(HSIP4+) ; also on sheet 7
PEX_PE1_RXP5: J4.A39(HSIP5+) ; also on sheet 7
PEX_PE1_RXP6: J4.A43(HSIP6+) ; also on sheet 7
PEX_PE1_RXP7: J4.A47(HSIP7+) ; also on sheet 7
PEX_PE1_RXP8: J4.A52(HSIP8+) ; also on sheet 7
PEX_PE1_RXP9: J4.A56(HSIP9+) ; also on sheet 7
PEX_PE1_RXP10: J4.A60(HSIP10+) ; also on sheet 7
PEX_PE1_RXP11: J4.A64(HSIP11+) ; also on sheet 7
PEX_PE1_RXP12: J4.A68(HSIP12+) ; also on sheet 7
PEX_PE1_RXP13: J4.A72(HSIP13+) ; also on sheet 7
PEX_PE1_RXP14: J4.A76(HSIP14) ; also on sheet 7
PEX_PE1_RXP15: J4.A80(HSIP15+) ; also on sheet 7
PEX_PE1_TXN0: C571.1 ; also on sheet 7
PEX_PE1_TXN0_C: C571.2 J4.B15(HSOP0-)
PEX_PE1_TXN1: C573.1 ; also on sheet 7
PEX_PE1_TXN1_C: C573.2 J4.B20(HSOP1-)
PEX_PE1_TXN2: C575.1 ; also on sheet 7
PEX_PE1_TXN2_C: C575.2 J4.B24(HSOP2-)
PEX_PE1_TXN3: C577.1 ; also on sheet 7
PEX_PE1_TXN3_C: C577.2 J4.B28(HSOP3-)
PEX_PE1_TXN4: C579.1 ; also on sheet 7
PEX_PE1_TXN4_C: C579.2 J4.B34(HSOP4-)
PEX_PE1_TXN5: C581.1 ; also on sheet 7
PEX_PE1_TXN5_C: C581.2 J4.B38(HSOP5-)
PEX_PE1_TXN6: C583.1 ; also on sheet 7
PEX_PE1_TXN6_C: C583.2 J4.B42(HSOP6-)
PEX_PE1_TXN7: C585.1 ; also on sheet 7
PEX_PE1_TXN7_C: C585.2 J4.B46(HSOP7-)
PEX_PE1_TXN8: C587.1 ; also on sheet 7
PEX_PE1_TXN8_C: C587.2 J4.B51(HSOP8-)
PEX_PE1_TXN9: C589.1 ; also on sheet 7
PEX_PE1_TXN9_C: C589.2 J4.B55(HSOP9-)
PEX_PE1_TXN10: C591.1 ; also on sheet 7
PEX_PE1_TXN10_C: C591.2 J4.B59(HSOP10-)
PEX_PE1_TXN11: C593.1 ; also on sheet 7
PEX_PE1_TXN11_C: C593.2 J4.B63(HSOP11-)
PEX_PE1_TXN12: C595.1 ; also on sheet 7
PEX_PE1_TXN12_C: C595.2 J4.B67(HSOP12-)
PEX_PE1_TXN13: C597.1 ; also on sheet 7
PEX_PE1_TXN13_C: C597.2 J4.B71(HSOP13-)
PEX_PE1_TXN14: C599.1 ; also on sheet 7
PEX_PE1_TXN14_C: C599.2 J4.B75(HSOP14-)
PEX_PE1_TXN15: C601.1 ; also on sheet 7
PEX_PE1_TXN15_C: C601.2 J4.B79(HSOP15-)
PEX_PE1_TXP0: C570.1 ; also on sheet 7
PEX_PE1_TXP0_C: C570.2 J4.B14(HSOP0+)
PEX_PE1_TXP1: C572.1 ; also on sheet 7
PEX_PE1_TXP1_C: C572.2 J4.B19(HSOP1+)
PEX_PE1_TXP2: C574.1 ; also on sheet 7
PEX_PE1_TXP2_C: C574.2 J4.B23(HSOP2+)
PEX_PE1_TXP3: C576.1 ; also on sheet 7
PEX_PE1_TXP3_C: C576.2 J4.B27(HSOP3+)
PEX_PE1_TXP4: C578.1 ; also on sheet 7
PEX_PE1_TXP4_C: C578.2 J4.B33(HSOP4+)
PEX_PE1_TXP5: C580.1 ; also on sheet 7
PEX_PE1_TXP5_C: C580.2 J4.B37(HSOP5+)
PEX_PE1_TXP6: C582.1 ; also on sheet 7
PEX_PE1_TXP6_C: C582.2 J4.B41(HSOP6+)
PEX_PE1_TXP7: C584.1 ; also on sheet 7
PEX_PE1_TXP7_C: C584.2 J4.B45(HSOP7+)
PEX_PE1_TXP8: C586.1 ; also on sheet 7
PEX_PE1_TXP8_C: C586.2 J4.B50(HSOP8+)
PEX_PE1_TXP9: C588.1 ; also on sheet 7
PEX_PE1_TXP9_C: C588.2 J4.B54(HSOP9+)
PEX_PE1_TXP10: C590.1 ; also on sheet 7
PEX_PE1_TXP10_C: C590.2 J4.B58(HSOP10+)
PEX_PE1_TXP11: C592.1 ; also on sheet 7
PEX_PE1_TXP11_C: C592.2 J4.B62(HSOP11+)
PEX_PE1_TXP12: C594.1 ; also on sheet 7
PEX_PE1_TXP12_C: C594.2 J4.B66(HSOP12+)
PEX_PE1_TXP13: C596.1 ; also on sheet 7
PEX_PE1_TXP13_C: C596.2 J4.B70(HSOP13+)
PEX_PE1_TXP14: C598.1 ; also on sheet 7
PEX_PE1_TXP14_C: C598.2 J4.B74(HSOP14+)
PEX_PE1_TXP15: C600.1 ; also on sheet 7
PEX_PE1_TXP15_C: C600.2 J4.B78(HSOP15+)
PU_9FG830A_14M_SEL: R411.1 R413.1 U5.27(^SEL14M_25M#)
PU_9FG830A_B_14M_SEL: R468.1 R470.1 U6.27(^SEL14M_25M#)
PU_PLX_CLK_EN: R404.1 U5.43(vOE_0)
PU_PLXB_CLK_EN: R457.1 U6.43(vOE_0)
RST_IPASSHD_A1_R_N: J2.B10(SB11) R1197.2 U107.3(2A)
RST_IPASSHD_A3_R_N: J1.B10(SB11) R1196.2 U107.1(1A)
RST_IPASSHD_A1234_N: R503.1 R506.1 R1181.2
RST_IPASSHD_A_N: R1181.1 ; also on sheet 54
RST_IPASSHD_B1_R_N: J40.B10(SB11) R1200.2 U108.3(2A)
RST_IPASSHD_B3_R_N: J39.B10(SB11) R1199.2 U108.1(1A)
RST_IPASSHD_B1234_N: R1198.1 R1201.2 R1202.1
RST_IPASSHD_B_N: R1201.1 ; also on sheet 54
RST_PCIE_SLOT_0_N: R518.2 ; also on sheet 54
RST_PCIE_SLOT_0_R_N: J3.A11(PERST#) R518.1
RST_PCIE_SLOT_1_N: R526.2 ; also on sheet 54
RST_PCIE_SLOT_1_R_N: J4.A11(PERST#) R526.1
SMB_CLK_SCL_R: R421.2 R429.2 U5.24(SCLK)
SMB_CLK_SDA_R: R422.2 R430.2 U5.23(SDATA)
SMB_CLKB_SCL_R: R478.2 R486.2 U6.24(SCLK)
SMB_CLKB_SDA_R: R479.2 R487.2 U6.23(SDATA)
SMB_CLKGEN_B_SCL: R486.1 ; also on sheet 45
SMB_CLKGEN_B_SDA: R487.1 ; also on sheet 45
SMB_CLKGEN_SCL: R429.1 ; also on sheet 45
SMB_CLKGEN_SDA: R430.1 ; also on sheet 45
SMB_PE0_SCL: R516.1 ; also on sheet 45
SMB_PE0_SCL_R: J3.B5(SMCLK) R513.2 R516.2
SMB_PE0_SDA: R517.1 ; also on sheet 45
SMB_PE0_SDA_R: J3.B6(SMDATA) R514.2 R517.2
SMB_PE1_SCL: R524.1 ; also on sheet 45
SMB_PE1_SCL_R: J4.B5(SMCLK) R521.2 R524.2
SMB_PE1_SDA: R525.1 ; also on sheet 45
SMB_PE1_SDA_R: J4.B6(SMDATA) R522.2 R525.2
TP_CLK_100M_DIF7_RN: U5.9(DIF_7#)
TP_CLK_100M_DIF7_RP: U5.8(DIF_7)
TP_CLK_FS0: R433.1 R434.1 U5.45(vFS0)
TP_CLK_FS1: R431.1 R432.1 U5.44(vFS1)
TP_CLK_FS2: R425.1 R428.1 U5.6(vFS2)
TP_CLK_REFOUT: U5.5(REFOUT)
TP_CLKB_100M_DIF7_RN: U6.9(DIF_7#)
TP_CLKB_100M_DIF7_RP: U6.8(DIF_7)
TP_CLKB_FS0: R490.1 R491.1 U6.45(vFS0)
TP_CLKB_FS1: R488.1 R489.1 U6.44(vFS1)
TP_CLKB_FS2: R482.1 R485.1 U6.6(vFS2)
TP_CLKB_REFOUT: U6.5(REFOUT)
TP_PE_SLOT0_JTAG_TDO: J3.A7(JTAG4)
TP_PE_SLOT0_RSVD_B82: J3.B82(RSVD3)
TP_PE_SLOT1_JTAG_TDO: J4.A7(JTAG4)
TP_PE_SLOT1_RSVD_B82: J4.B82(RSVD3)
TP_SLOT0_JTAG_TCK: J3.A5(JTAG2)
TP_SLOT0_JTAG_TDI: J3.A6(JTAG3)
TP_SLOT0_JTAG_TMS: J3.A8(JTAG5)
TP_SLOT0_JTAG_TRST_N: J3.B9(JTAG1)
TP_SLOT0_RSVD_A19: J3.A19(RSVD4)
TP_SLOT0_RSVD_A32: J3.A32(RSVD5)
TP_SLOT0_RSVD_A33: J3.A33(RSVD6)
TP_SLOT0_RSVD_A50: J3.A50(RSVD7)
TP_SLOT0_RSVD_B30: J3.B30(RSVD2)
TP_SLOT0_WAKE_N: J3.B11(WAKE_N)
TP_SLOT1_JTAG_TCK: J4.A5(JTAG2)
TP_SLOT1_JTAG_TDI: J4.A6(JTAG3)
TP_SLOT1_JTAG_TMS: J4.A8(JTAG5)
TP_SLOT1_JTAG_TRST_N: J4.B9(JTAG1)
TP_SLOT1_RSVD_A19: J4.A19(RSVD4)
TP_SLOT1_RSVD_A32: J4.A32(RSVD5)
TP_SLOT1_RSVD_A33: J4.A33(RSVD6)
TP_SLOT1_RSVD_A50: J4.A50(RSVD7)
TP_SLOT1_RSVD_B30: J4.B30(RSVD2)
TP_SLOT1_WAKE_N: J4.B11(WAKE_N)
N33809929: R506.2 U107.7(1Y)
N33810328: R503.2 U107.5(2Y)
N33812953: R1202.2 U108.7(1Y)
N33812971: R1198.2 U108.5(2Y)

Not connected (* = marked no-connect by the designer): J1 A1(SB7) A2(SB0) A10(SB15) A11(SB8) B1(SB3) B11(SB9) C2(SB2) C10(SB12) C11(SB10) D1(SB5) D2(SB6) D10(SB13) D11(SB14); J2 A1(SB7) A2(SB0) A10(SB15) A11(SB8) B1(SB3) B2(SB1) B11(SB9) C1(SB4) C2(SB2) C10(SB12) C11(SB10) D1(SB5) D2(SB6) D10(SB13) D11(SB14); J39 A1(SB7) A2(SB0) A10(SB15) A11(SB8) B1(SB3) B11(SB9) C2(SB2) C10(SB12) C11(SB10) D1(SB5) D2(SB6) D10(SB13) D11(SB14); J40 A1(SB7) A2(SB0) A10(SB15) A11(SB8) B1(SB3) B2(SB1) B11(SB9) C1(SB4) C2(SB2) C10(SB12) C11(SB10) D1(SB5) D2(SB6) D10(SB13) D11(SB14); U107 2(3Y); U108 2(3Y); U109 1(NC)*; U111 1(NC)*

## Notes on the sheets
sheet 32
- GPU PCIE X16 Slot 0
